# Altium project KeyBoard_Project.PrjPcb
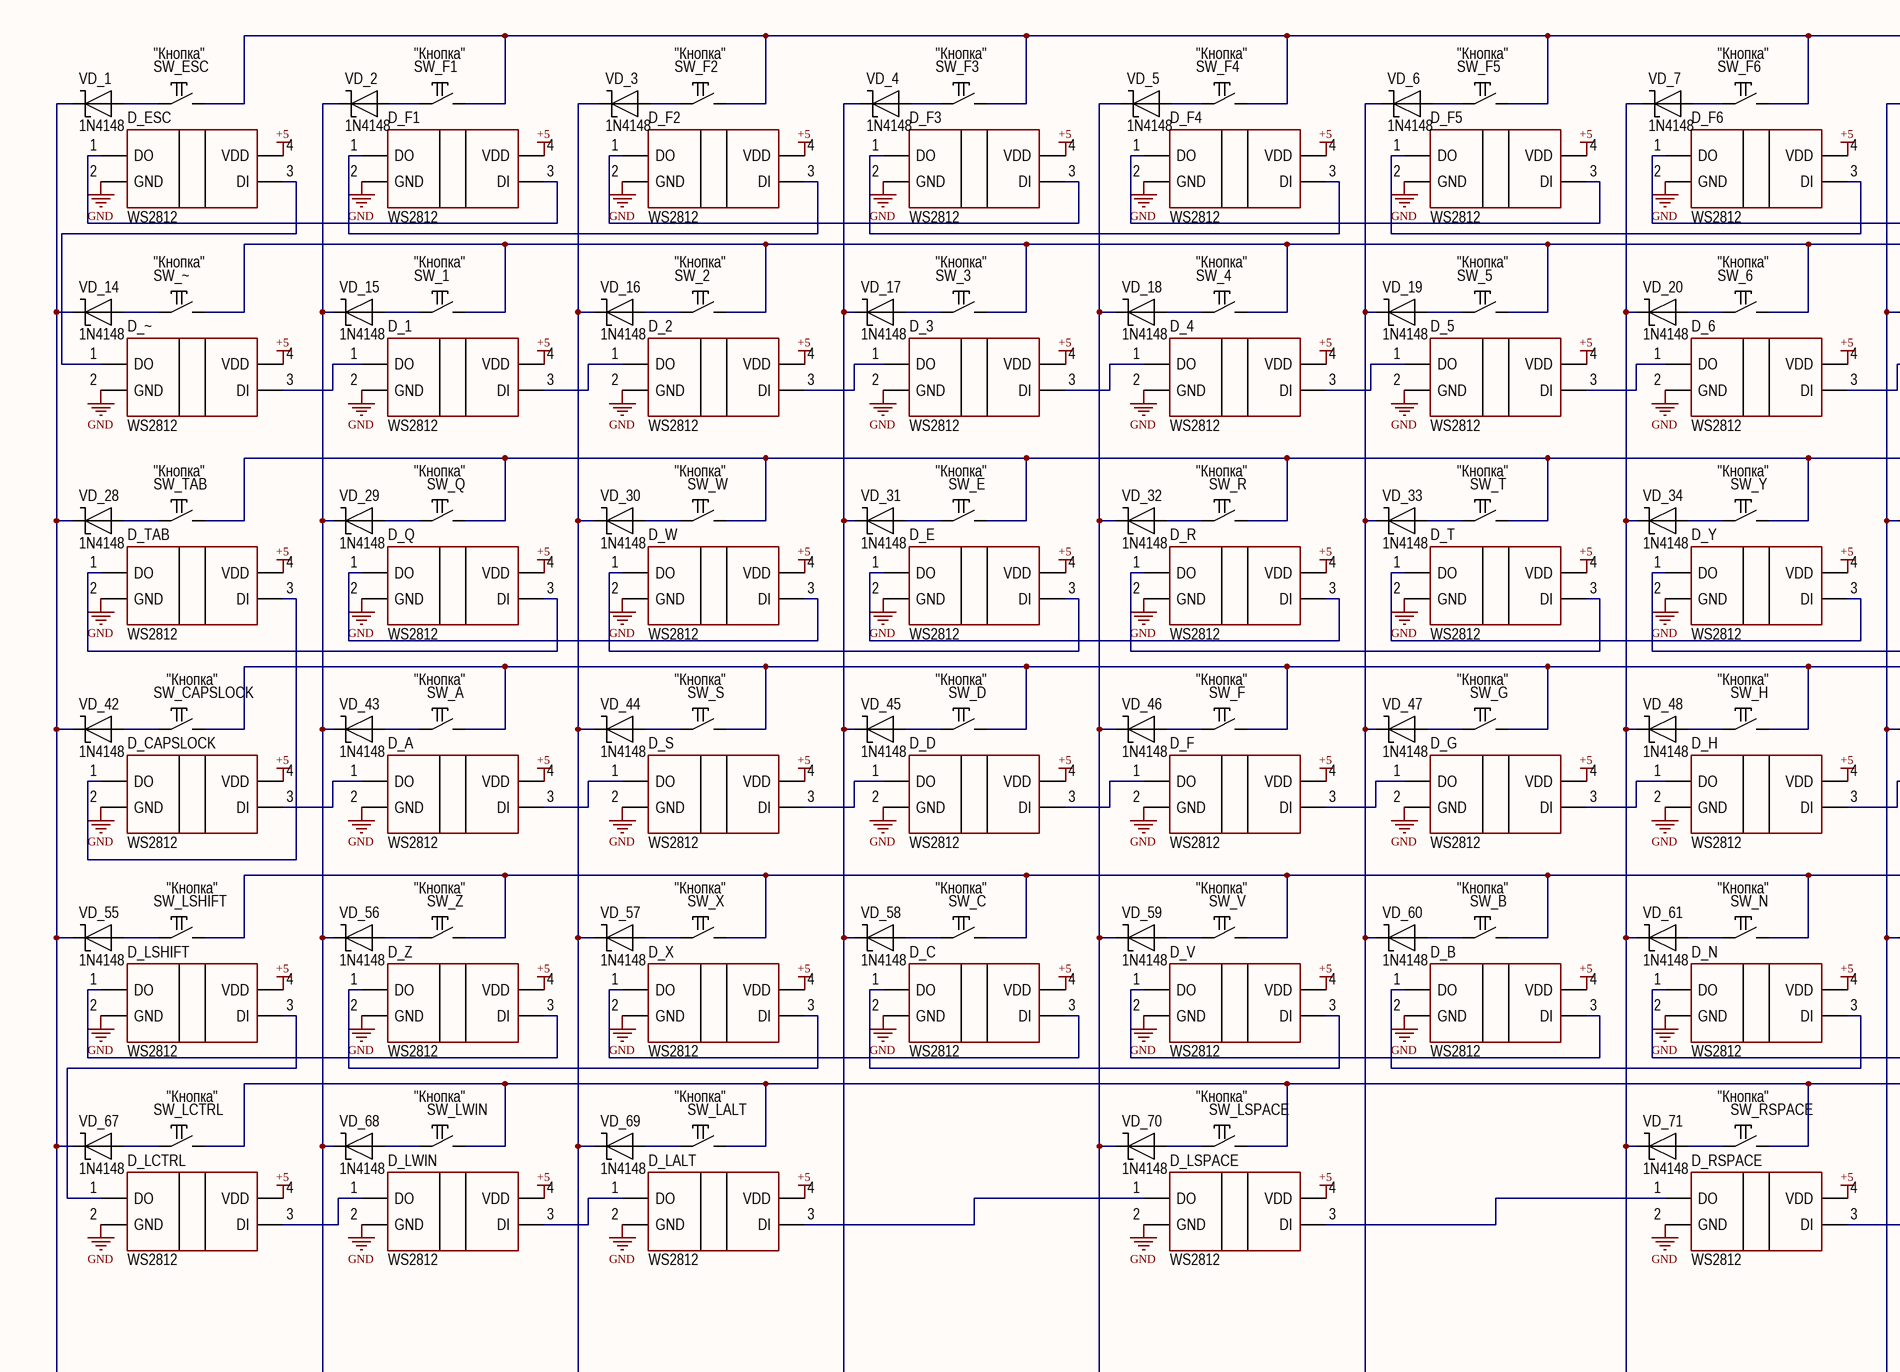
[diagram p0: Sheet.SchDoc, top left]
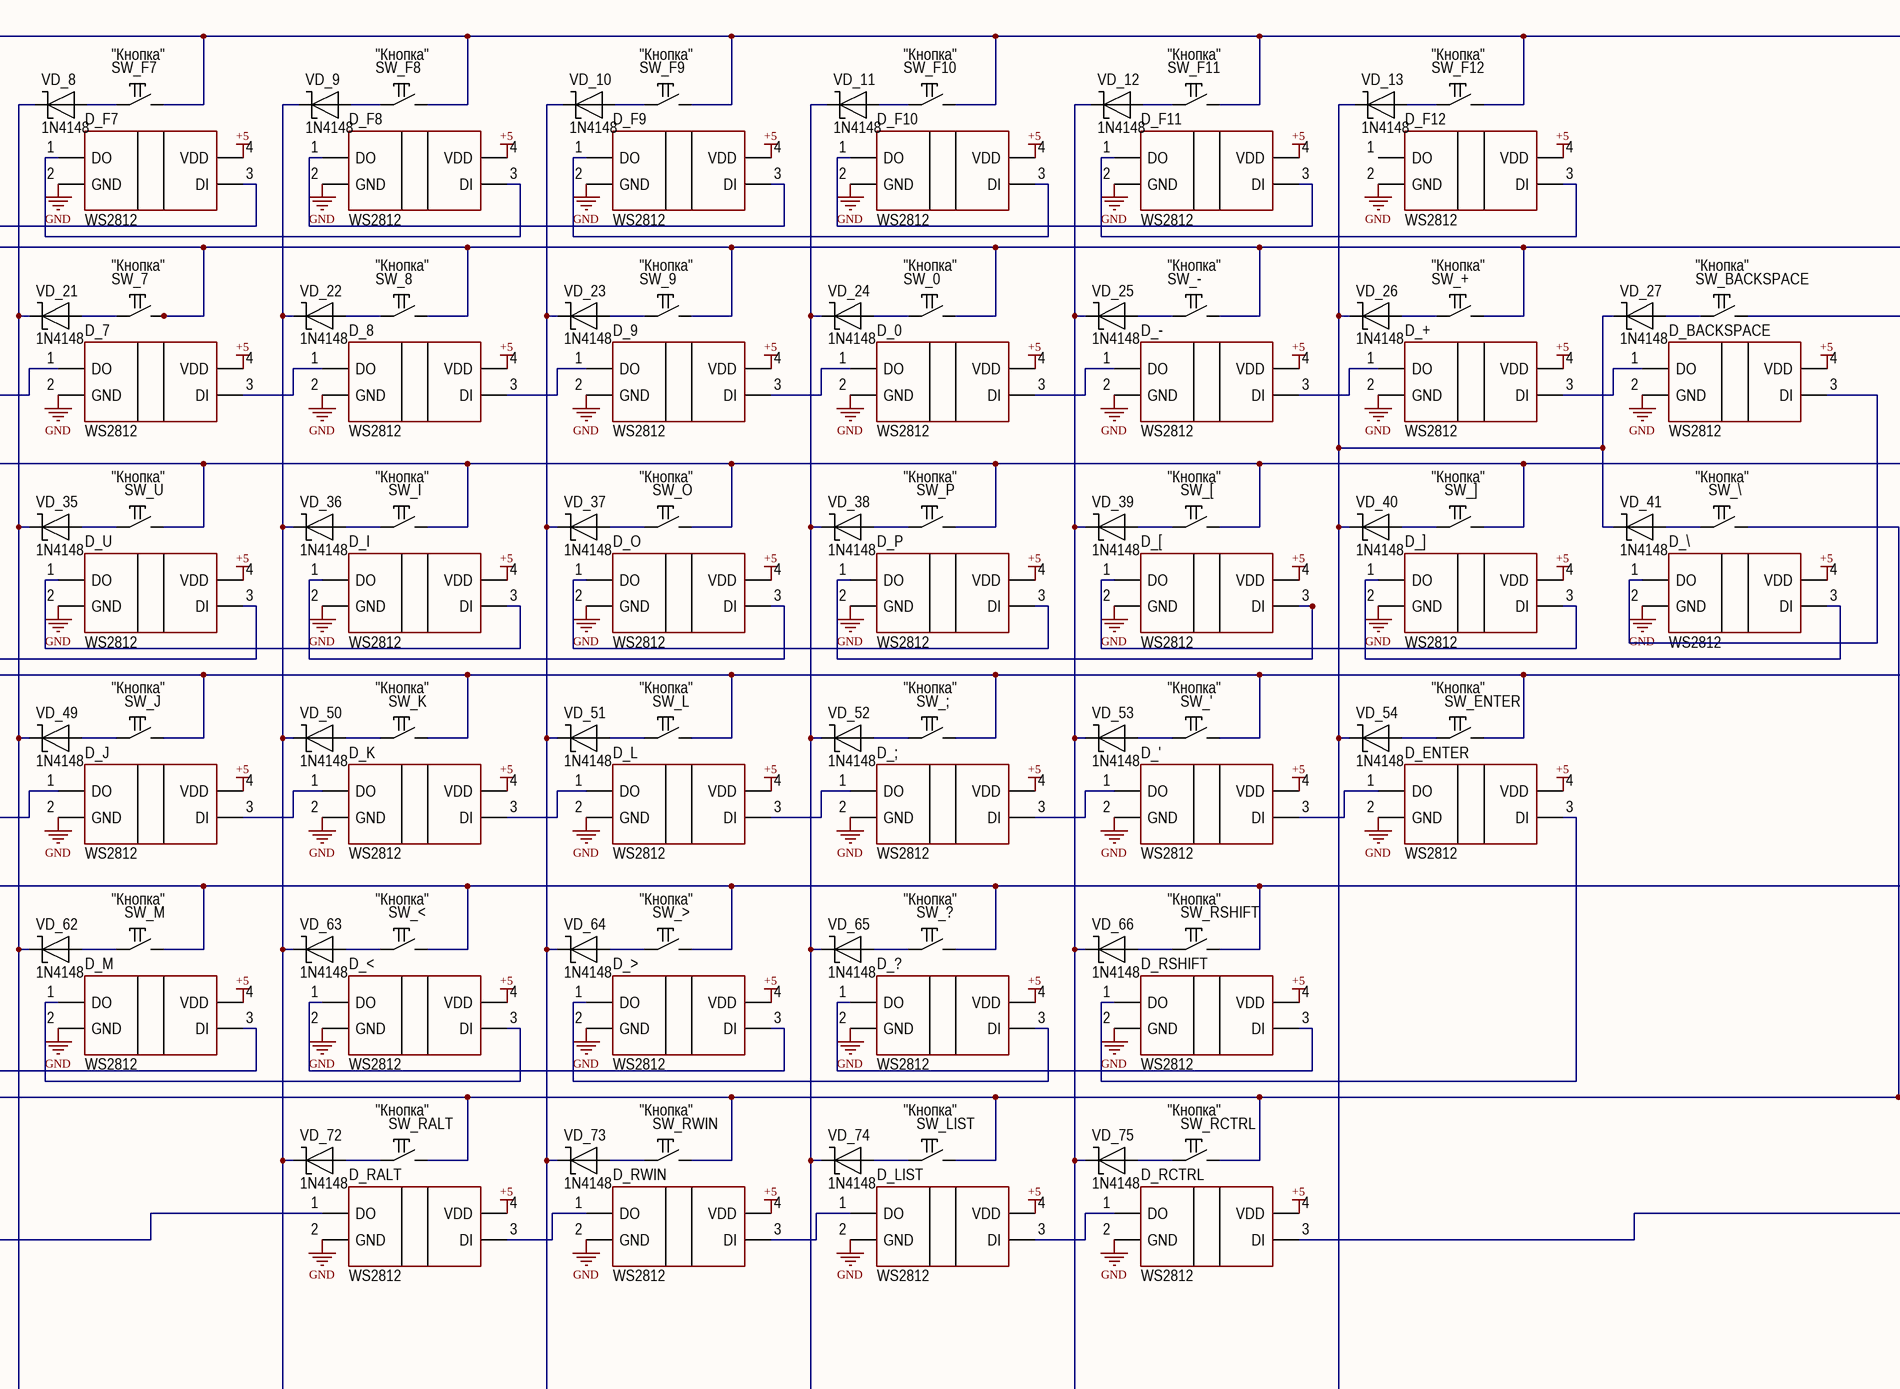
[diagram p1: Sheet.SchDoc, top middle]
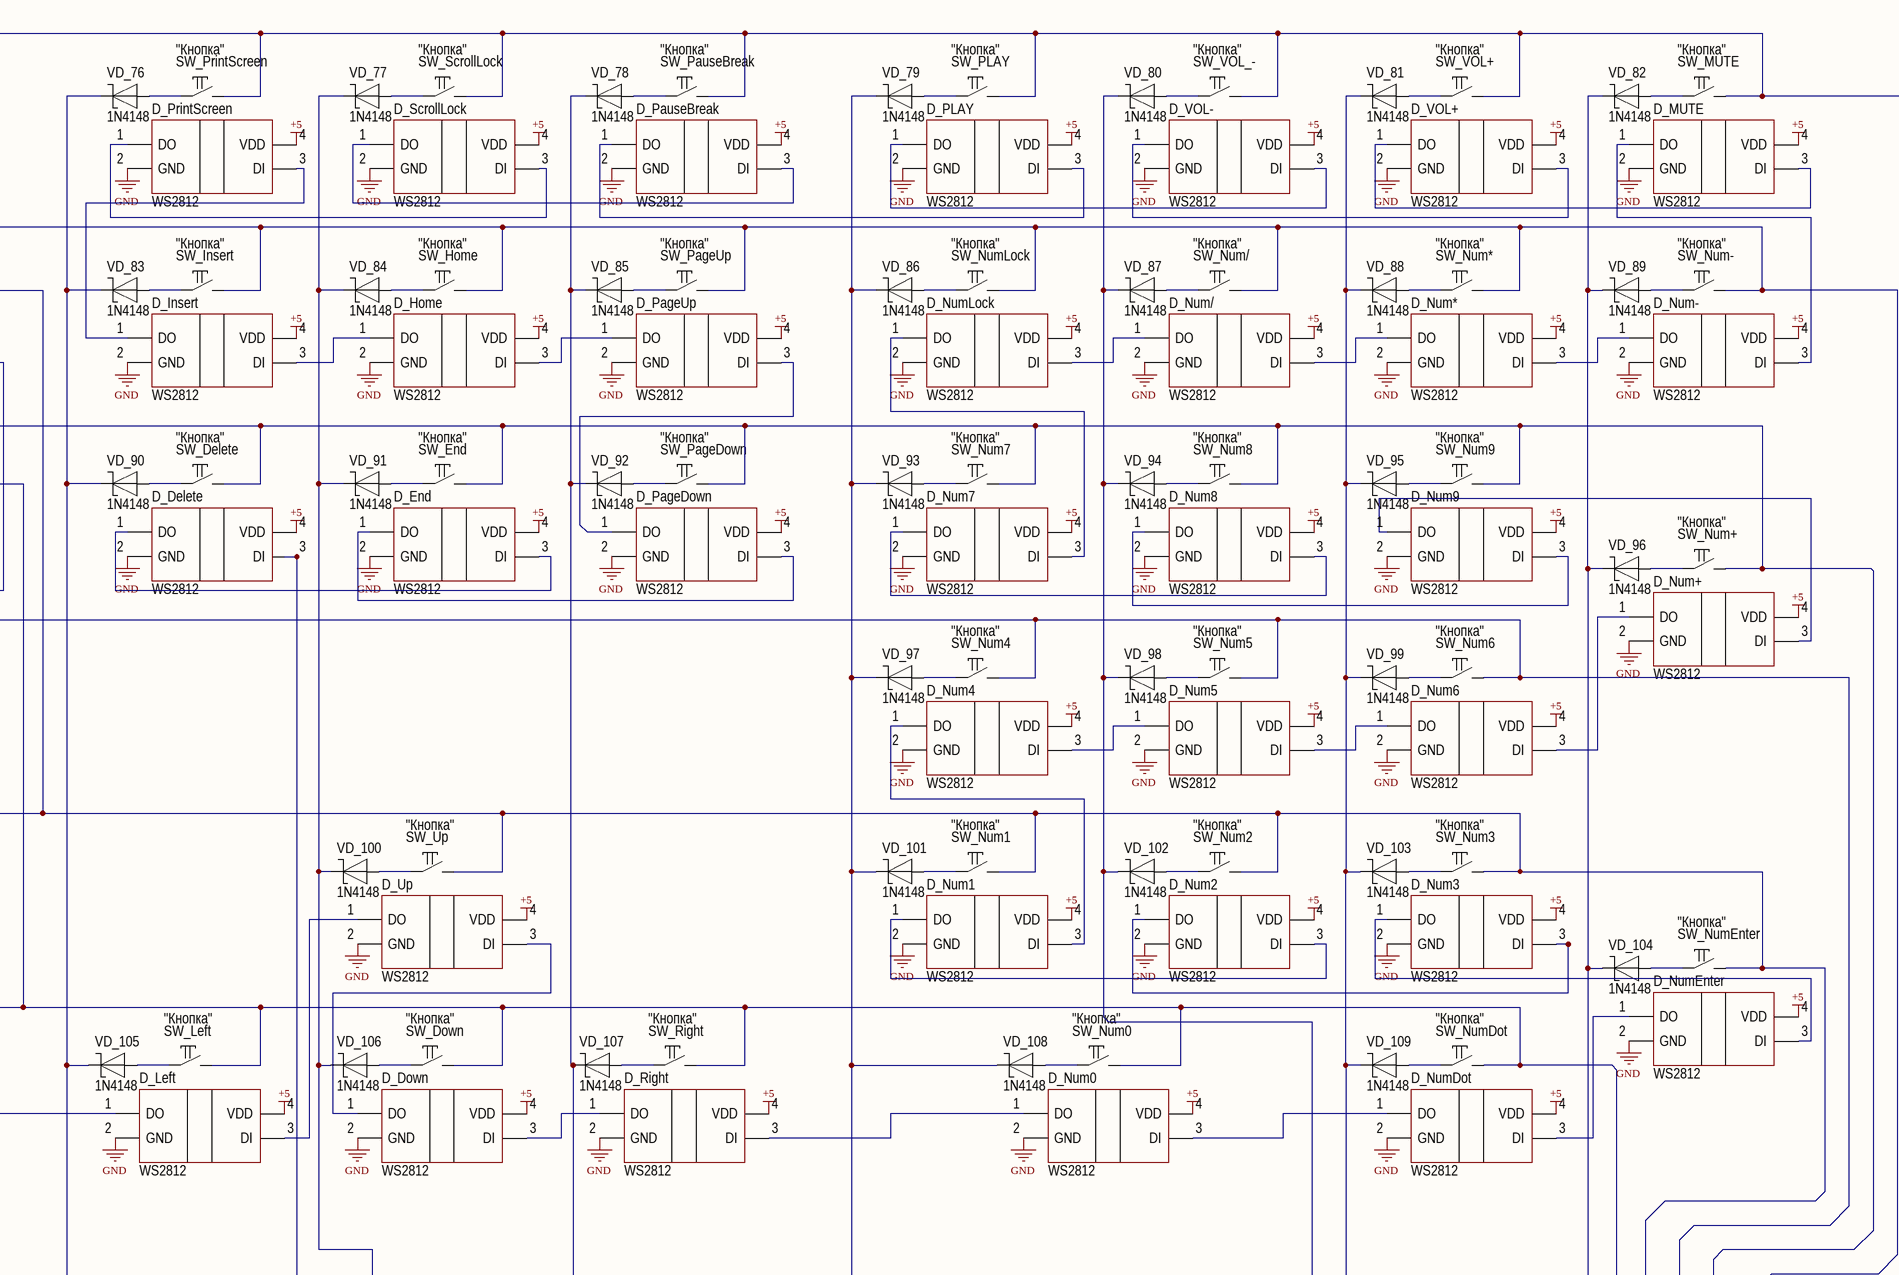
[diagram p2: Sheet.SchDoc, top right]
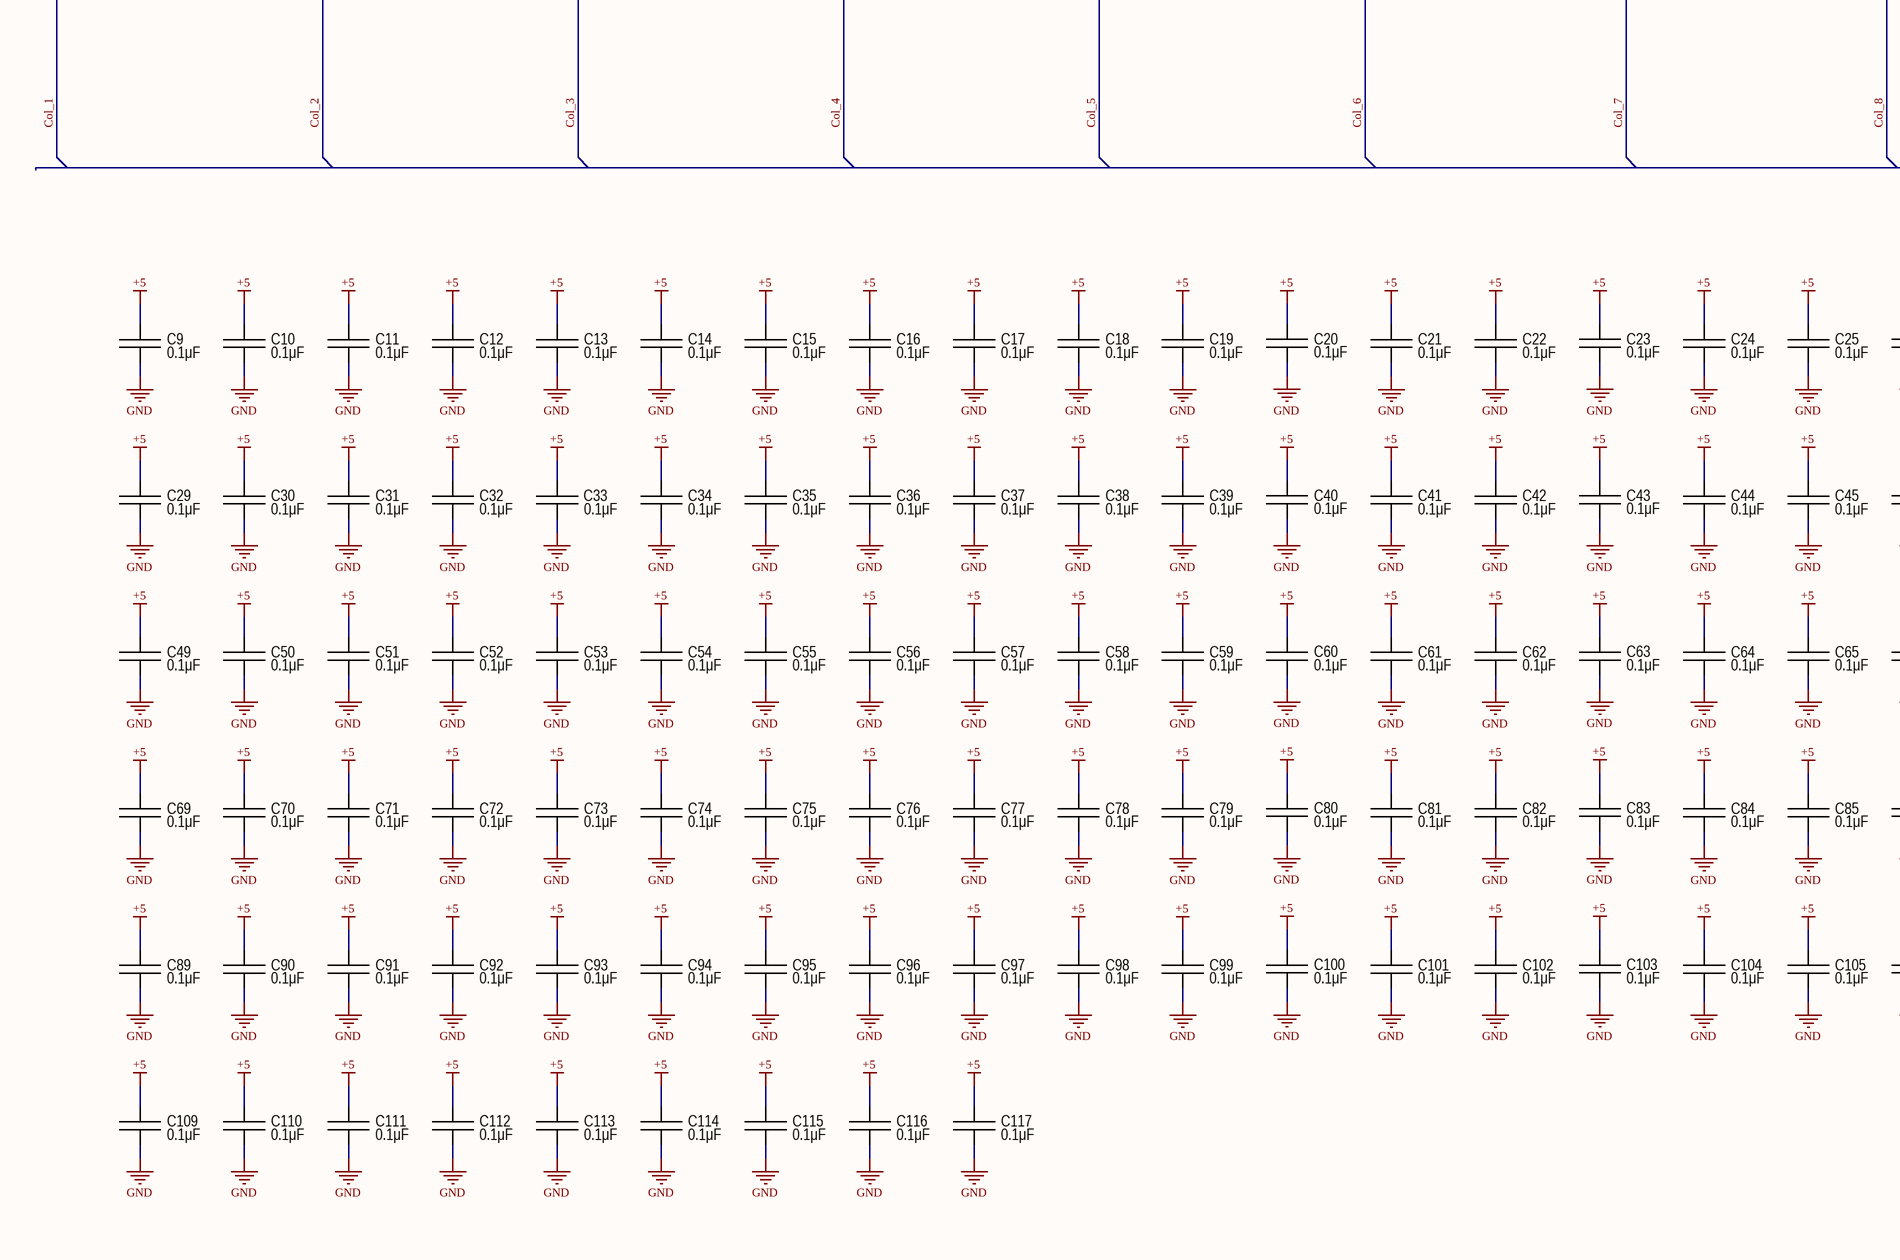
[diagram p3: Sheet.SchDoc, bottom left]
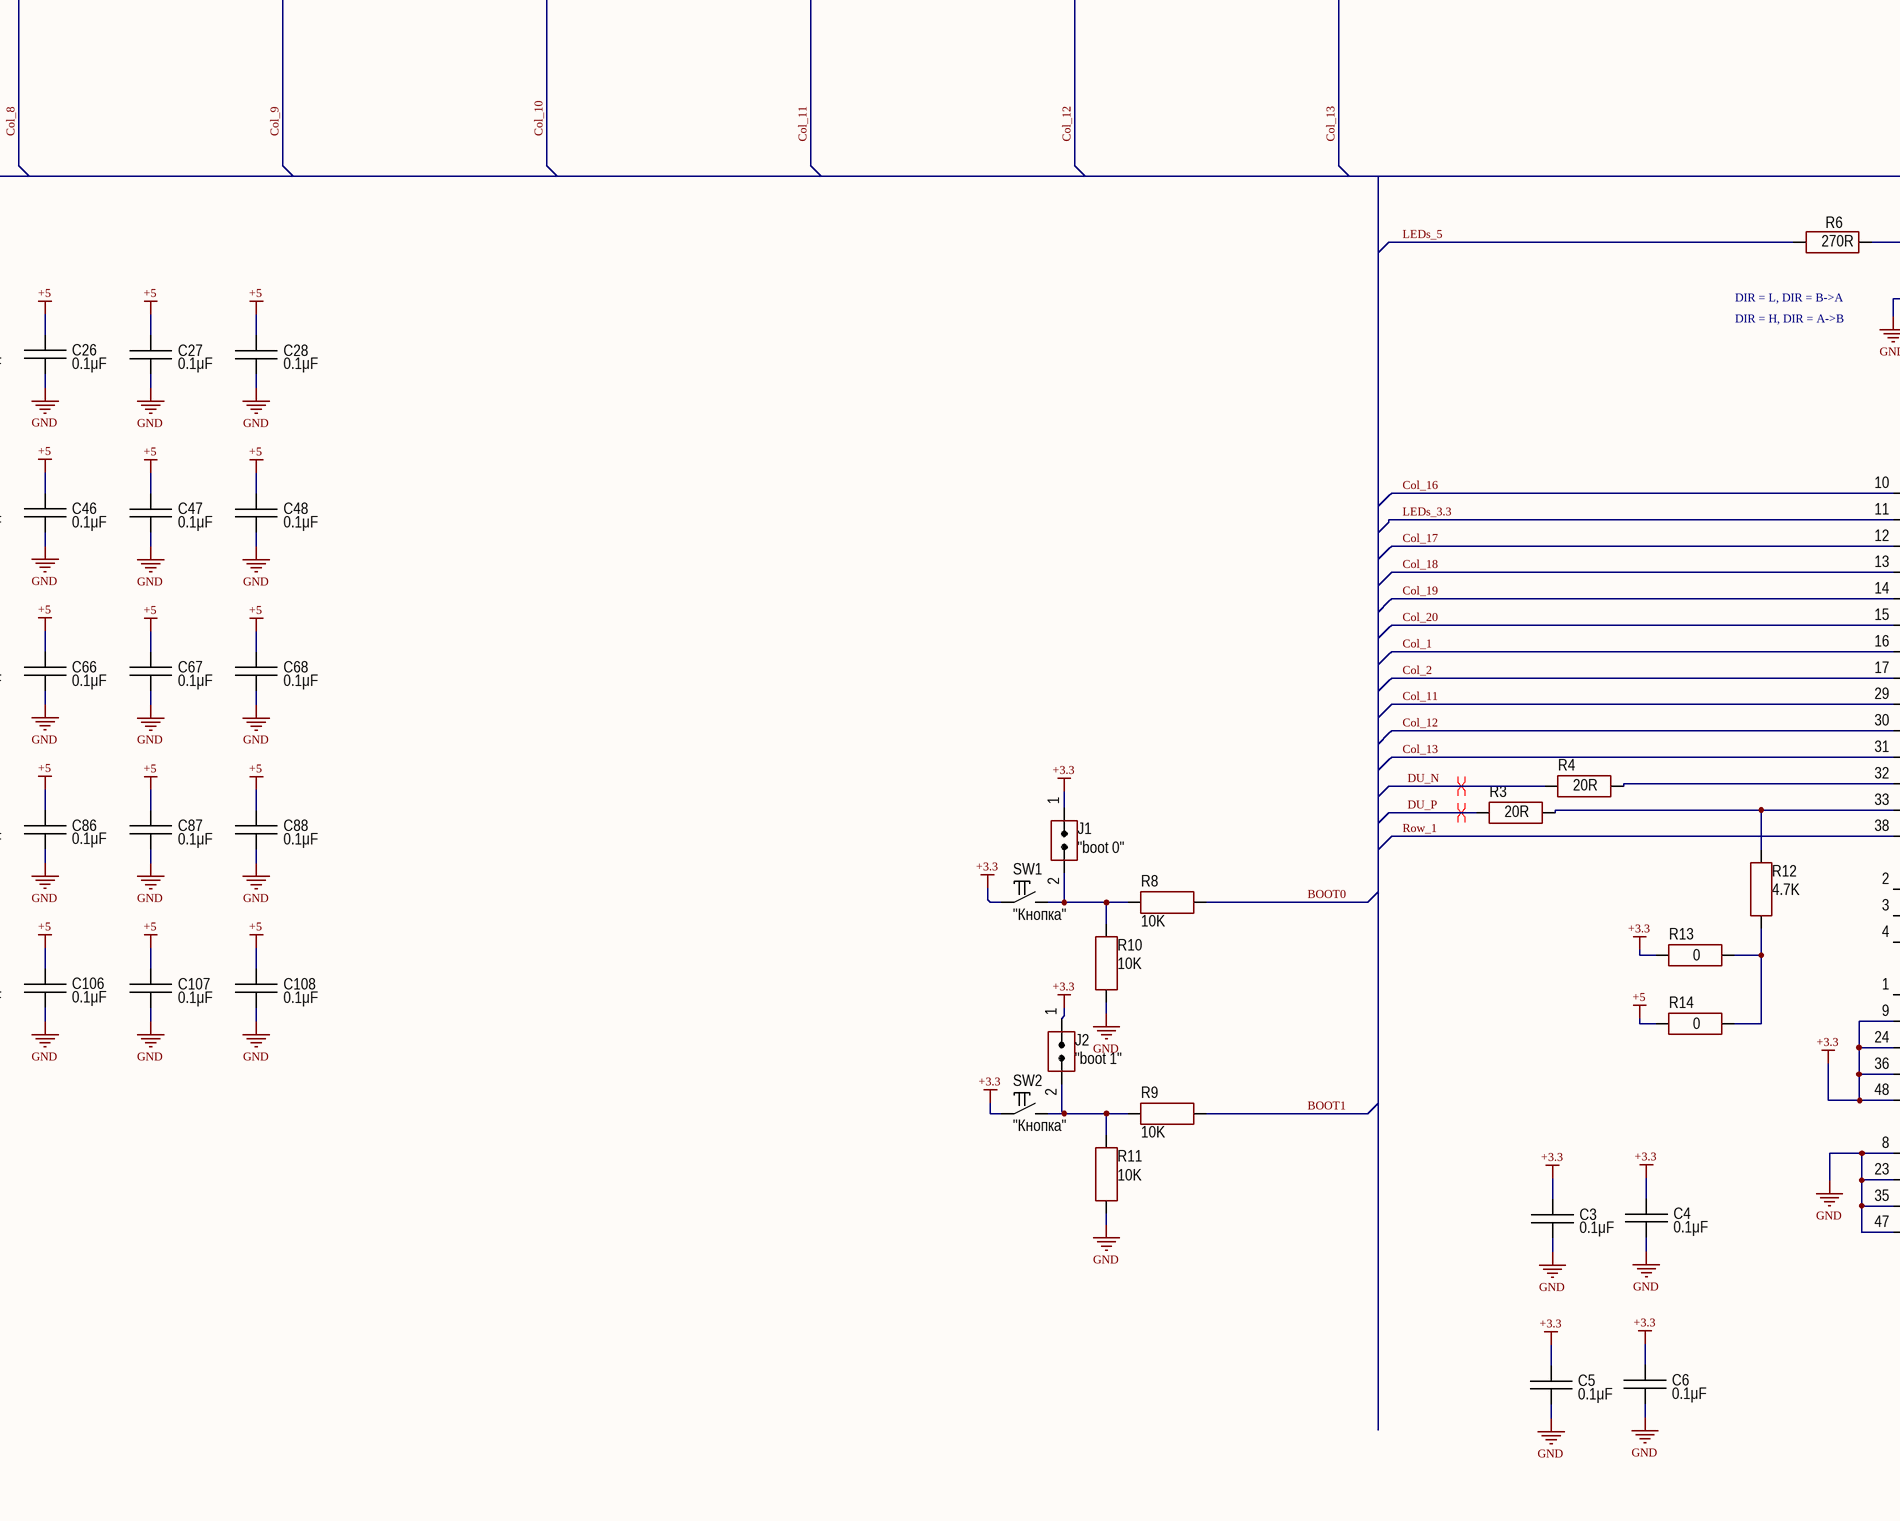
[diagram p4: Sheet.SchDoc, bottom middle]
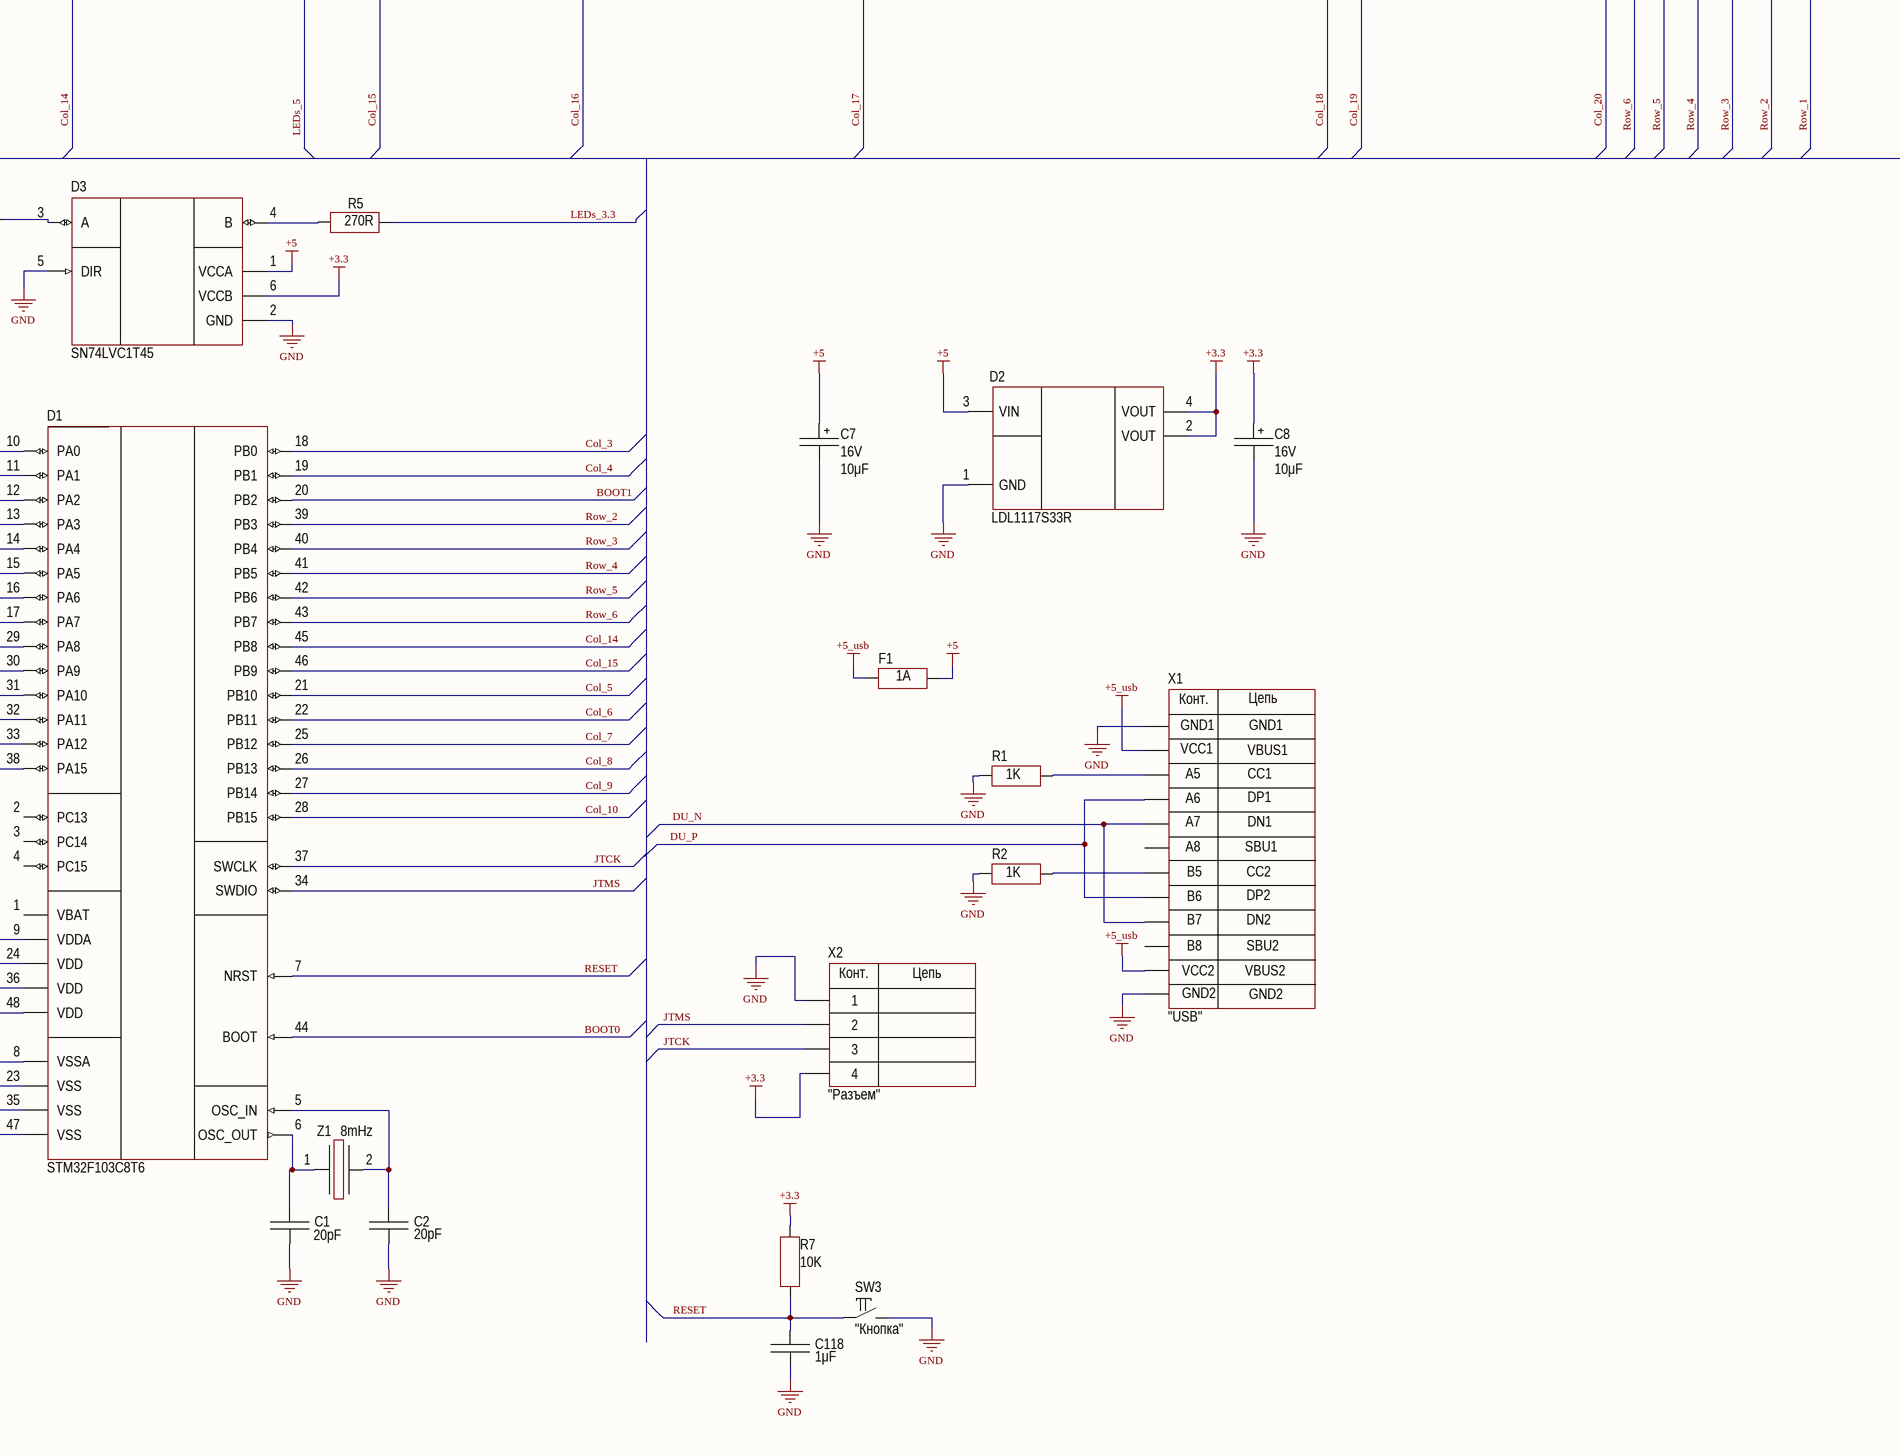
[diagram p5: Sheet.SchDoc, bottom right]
1 sheet, 471 parts. Net scope: global (net labels, ports and power ports of the same name join across sheets).
Board file: PCB.PcbDoc

## Sheet Sheet.SchDoc
size A0

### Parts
C1  value 20pF  [CAP: 0603]
C2  value 20pF  [CAP: 0603]
C3  value 0.1μF  [CAP: 0603]
C4  value 0.1μF  [CAP: 0603]
C5  value 0.1μF  [CAP: 0603]
C6  value 0.1μF  [CAP: 0603]
C7  value 10μF  Voltage: 16V  [CAP: TANTAL-A]
C8  value 10μF  Voltage: 16V  [CAP: TANTAL-A]
C9  value 0.1μF  [CAP: 0603]
C10  value 0.1μF  [CAP: 0603]
C11  value 0.1μF  [CAP: 0603]
C12  value 0.1μF  [CAP: 0603]
C13  value 0.1μF  [CAP: 0603]
C14  value 0.1μF  [CAP: 0603]
C15  value 0.1μF  [CAP: 0603]
C16  value 0.1μF  [CAP: 0603]
C17  value 0.1μF  [CAP: 0603]
C18  value 0.1μF  [CAP: 0603]
C19  value 0.1μF  [CAP: 0603]
C20  value 0.1μF  [CAP: 0603]
C21  value 0.1μF  [CAP: 0603]
C22  value 0.1μF  [CAP: 0603]
C23  value 0.1μF  [CAP: 0603]
C24  value 0.1μF  [CAP: 0603]
C25  value 0.1μF  [CAP: 0603]
C26  value 0.1μF  [CAP: 0603]
C27  value 0.1μF  [CAP: 0603]
C28  value 0.1μF  [CAP: 0603]
C29  value 0.1μF  [CAP: 0603]
C30  value 0.1μF  [CAP: 0603]
C31  value 0.1μF  [CAP: 0603]
C32  value 0.1μF  [CAP: 0603]
C33  value 0.1μF  [CAP: 0603]
C34  value 0.1μF  [CAP: 0603]
C35  value 0.1μF  [CAP: 0603]
C36  value 0.1μF  [CAP: 0603]
C37  value 0.1μF  [CAP: 0603]
C38  value 0.1μF  [CAP: 0603]
C39  value 0.1μF  [CAP: 0603]
C40  value 0.1μF  [CAP: 0603]
C41  value 0.1μF  [CAP: 0603]
C42  value 0.1μF  [CAP: 0603]
C43  value 0.1μF  [CAP: 0603]
C44  value 0.1μF  [CAP: 0603]
C45  value 0.1μF  [CAP: 0603]
C46  value 0.1μF  [CAP: 0603]
C47  value 0.1μF  [CAP: 0603]
C48  value 0.1μF  [CAP: 0603]
C49  value 0.1μF  [CAP: 0603]
C50  value 0.1μF  [CAP: 0603]
C51  value 0.1μF  [CAP: 0603]
C52  value 0.1μF  [CAP: 0603]
C53  value 0.1μF  [CAP: 0603]
C54  value 0.1μF  [CAP: 0603]
C55  value 0.1μF  [CAP: 0603]
C56  value 0.1μF  [CAP: 0603]
C57  value 0.1μF  [CAP: 0603]
C58  value 0.1μF  [CAP: 0603]
C59  value 0.1μF  [CAP: 0603]
C60  value 0.1μF  [CAP: 0603]
C61  value 0.1μF  [CAP: 0603]
C62  value 0.1μF  [CAP: 0603]
C63  value 0.1μF  [CAP: 0603]
C64  value 0.1μF  [CAP: 0603]
C65  value 0.1μF  [CAP: 0603]
C66  value 0.1μF  [CAP: 0603]
C67  value 0.1μF  [CAP: 0603]
C68  value 0.1μF  [CAP: 0603]
C69  value 0.1μF  [CAP: 0603]
C70  value 0.1μF  [CAP: 0603]
C71  value 0.1μF  [CAP: 0603]
C72  value 0.1μF  [CAP: 0603]
C73  value 0.1μF  [CAP: 0603]
C74  value 0.1μF  [CAP: 0603]
C75  value 0.1μF  [CAP: 0603]
C76  value 0.1μF  [CAP: 0603]
C77  value 0.1μF  [CAP: 0603]
C78  value 0.1μF  [CAP: 0603]
C79  value 0.1μF  [CAP: 0603]
C80  value 0.1μF  [CAP: 0603]
C81  value 0.1μF  [CAP: 0603]
C82  value 0.1μF  [CAP: 0603]
C83  value 0.1μF  [CAP: 0603]
C84  value 0.1μF  [CAP: 0603]
C85  value 0.1μF  [CAP: 0603]
C86  value 0.1μF  [CAP: 0603]
C87  value 0.1μF  [CAP: 0603]
C88  value 0.1μF  [CAP: 0603]
C89  value 0.1μF  [CAP: 0603]
C90  value 0.1μF  [CAP: 0603]
C91  value 0.1μF  [CAP: 0603]
C92  value 0.1μF  [CAP: 0603]
C93  value 0.1μF  [CAP: 0603]
C94  value 0.1μF  [CAP: 0603]
C95  value 0.1μF  [CAP: 0603]
C96  value 0.1μF  [CAP: 0603]
C97  value 0.1μF  [CAP: 0603]
C98  value 0.1μF  [CAP: 0603]
C99  value 0.1μF  [CAP: 0603]
C100  value 0.1μF  [CAP: 0603]
C101  value 0.1μF  [CAP: 0603]
C102  value 0.1μF  [CAP: 0603]
C103  value 0.1μF  [CAP: 0603]
C104  value 0.1μF  [CAP: 0603]
C105  value 0.1μF  [CAP: 0603]
C106  value 0.1μF  [CAP: 0603]
C107  value 0.1μF  [CAP: 0603]
C108  value 0.1μF  [CAP: 0603]
C109  value 0.1μF  [CAP: 0603]
C110  value 0.1μF  [CAP: 0603]
C111  value 0.1μF  [CAP: 0603]
C112  value 0.1μF  [CAP: 0603]
C113  value 0.1μF  [CAP: 0603]
C114  value 0.1μF  [CAP: 0603]
C115  value 0.1μF  [CAP: 0603]
C116  value 0.1μF  [CAP: 0603]
C117  value 0.1μF  [CAP: 0603]
C118  value 1μF  [CAP: 0603]
D1  (no value)  [48-LQFP]
D2  (no value)  [SOT223]
D3  IC CAN transceiver, 1Mbps, Half-duplex, 3...3.6V, -40...+85°C, 8-SOIC  [SOT23-6]  (value not drawn)
D_0  PartNumber: WS2812  [LED: 2020]
D_1  PartNumber: WS2812  [LED: 2020]
D_2  PartNumber: WS2812  [LED: 2020]
D_3  PartNumber: WS2812  [LED: 2020]
D_4  PartNumber: WS2812  [LED: 2020]
D_5  PartNumber: WS2812  [LED: 2020]
D_6  PartNumber: WS2812  [LED: 2020]
D_7  PartNumber: WS2812  [LED: 2020]
D_8  PartNumber: WS2812  [LED: 2020]
D_9  PartNumber: WS2812  [LED: 2020]
D_'  PartNumber: WS2812  [LED: 2020]
D_+  PartNumber: WS2812  [LED: 2020]
D_-  PartNumber: WS2812  [LED: 2020]
D_;  PartNumber: WS2812  [LED: 2020]
D_<  PartNumber: WS2812  [LED: 2020]
D_>  PartNumber: WS2812  [LED: 2020]
D_?  PartNumber: WS2812  [LED: 2020]
D_[  PartNumber: WS2812  [LED: 2020]
D_\  PartNumber: WS2812  [LED: 2020]
D_]  PartNumber: WS2812  [LED: 2020]
D_A  PartNumber: WS2812  [LED: 2020]
D_B  PartNumber: WS2812  [LED: 2020]
D_BACKSPACE  PartNumber: WS2812  [LED: 2020]
D_C  PartNumber: WS2812  [LED: 2020]
D_CAPSLOCK  PartNumber: WS2812  [LED: 2020]
D_D  PartNumber: WS2812  [LED: 2020]
D_Delete  PartNumber: WS2812  [LED: 2020]
D_Down  PartNumber: WS2812  [LED: 2020]
D_E  PartNumber: WS2812  [LED: 2020]
D_End  PartNumber: WS2812  [LED: 2020]
D_ENTER  PartNumber: WS2812  [LED: 2020]
D_ESC  PartNumber: WS2812  [LED: 2020]
D_F  PartNumber: WS2812  [LED: 2020]
D_F1  PartNumber: WS2812  [LED: 2020]
D_F2  PartNumber: WS2812  [LED: 2020]
D_F3  PartNumber: WS2812  [LED: 2020]
D_F4  PartNumber: WS2812  [LED: 2020]
D_F5  PartNumber: WS2812  [LED: 2020]
D_F6  PartNumber: WS2812  [LED: 2020]
D_F7  PartNumber: WS2812  [LED: 2020]
D_F8  PartNumber: WS2812  [LED: 2020]
D_F9  PartNumber: WS2812  [LED: 2020]
D_F10  PartNumber: WS2812  [LED: 2020]
D_F11  PartNumber: WS2812  [LED: 2020]
D_F12  PartNumber: WS2812  [LED: 2020]
D_G  PartNumber: WS2812  [LED: 2020]
D_H  PartNumber: WS2812  [LED: 2020]
D_Home  PartNumber: WS2812  [LED: 2020]
D_I  PartNumber: WS2812  [LED: 2020]
D_Insert  PartNumber: WS2812  [LED: 2020]
D_J  PartNumber: WS2812  [LED: 2020]
D_K  PartNumber: WS2812  [LED: 2020]
D_L  PartNumber: WS2812  [LED: 2020]
D_LALT  PartNumber: WS2812  [LED: 2020]
D_LCTRL  PartNumber: WS2812  [LED: 2020]
D_Left  PartNumber: WS2812  [LED: 2020]
D_LIST  PartNumber: WS2812  [LED: 2020]
D_LSHIFT  PartNumber: WS2812  [LED: 2020]
D_LSPACE  PartNumber: WS2812  [LED: 2020]
D_LWIN  PartNumber: WS2812  [LED: 2020]
D_M  PartNumber: WS2812  [LED: 2020]
D_MUTE  PartNumber: WS2812  [LED: 2020]
D_N  PartNumber: WS2812  [LED: 2020]
D_Num0  PartNumber: WS2812  [LED: 2020]
D_Num1  PartNumber: WS2812  [LED: 2020]
D_Num2  PartNumber: WS2812  [LED: 2020]
D_Num3  PartNumber: WS2812  [LED: 2020]
D_Num4  PartNumber: WS2812  [LED: 2020]
D_Num5  PartNumber: WS2812  [LED: 2020]
D_Num6  PartNumber: WS2812  [LED: 2020]
D_Num7  PartNumber: WS2812  [LED: 2020]
D_Num8  PartNumber: WS2812  [LED: 2020]
D_Num9  PartNumber: WS2812  [LED: 2020]
D_Num*  PartNumber: WS2812  [LED: 2020]
D_Num+  PartNumber: WS2812  [LED: 2020]
D_Num-  PartNumber: WS2812  [LED: 2020]
D_Num/  PartNumber: WS2812  [LED: 2020]
D_NumDot  PartNumber: WS2812  [LED: 2020]
D_NumEnter  PartNumber: WS2812  [LED: 2020]
D_NumLock  PartNumber: WS2812  [LED: 2020]
D_O  PartNumber: WS2812  [LED: 2020]
D_P  PartNumber: WS2812  [LED: 2020]
D_PageDown  PartNumber: WS2812  [LED: 2020]
D_PageUp  PartNumber: WS2812  [LED: 2020]
D_PauseBreak  PartNumber: WS2812  [LED: 2020]
D_PLAY  PartNumber: WS2812  [LED: 2020]
D_PrintScreen  PartNumber: WS2812  [LED: 2020]
D_Q  PartNumber: WS2812  [LED: 2020]
D_R  PartNumber: WS2812  [LED: 2020]
D_RALT  PartNumber: WS2812  [LED: 2020]
D_RCTRL  PartNumber: WS2812  [LED: 2020]
D_Right  PartNumber: WS2812  [LED: 2020]
D_RSHIFT  PartNumber: WS2812  [LED: 2020]
D_RSPACE  PartNumber: WS2812  [LED: 2020]
D_RWIN  PartNumber: WS2812  [LED: 2020]
D_S  PartNumber: WS2812  [LED: 2020]
D_ScrollLock  PartNumber: WS2812  [LED: 2020]
D_T  PartNumber: WS2812  [LED: 2020]
D_TAB  PartNumber: WS2812  [LED: 2020]
D_U  PartNumber: WS2812  [LED: 2020]
D_Up  PartNumber: WS2812  [LED: 2020]
D_V  PartNumber: WS2812  [LED: 2020]
D_VOL+  PartNumber: WS2812  [LED: 2020]
D_VOL-  PartNumber: WS2812  [LED: 2020]
D_W  PartNumber: WS2812  [LED: 2020]
D_X  PartNumber: WS2812  [LED: 2020]
D_Y  PartNumber: WS2812  [LED: 2020]
D_Z  PartNumber: WS2812  [LED: 2020]
D_~  PartNumber: WS2812  [LED: 2020]
F1  value 1A  [RES: 1206]  (hidden comment: Resistor film, 1A, , 1206, 0.25W, -55...+125°C)
J1  CommentText: "boot 0"  [CON: JUMPER x1]
J2  CommentText: "boot 1"  [CON: JUMPER x1]
R1  value 1K  [RES: 0603]  (hidden comment: Resistor film, 1K, , 0603, 0.1W, -55...+125°C)
R2  value 1K  [RES: 0603]  (hidden comment: Resistor film, 1K, , 0603, 0.1W, -55...+125°C)
R3  value 20R  [RES: 0603]  (hidden comment: Resistor film, 1K, , 0603, 0.1W, -55...+125°C)
R4  value 20R  [RES: 0603]  (hidden comment: Resistor film, 1K, , 0603, 0.1W, -55...+125°C)
R5  value 270R  [RES: 0603]  (hidden comment: Resistor film, 270R, , 0603, 0.1W, -55...+125°C)
R6  value 270R  [RES: 0603]  (hidden comment: Resistor film, 270R, , 0603, 0.1W, -55...+125°C)
R7  value 10K  [RES: 0603]  (hidden comment: Resistor film, 270R, , 0603, 0.1W, -55...+125°C)
R8  value 10K  [RES: 0603]  (hidden comment: Resistor film, 270R, , 0603, 0.1W, -55...+125°C)
R9  value 10K  [RES: 0603]  (hidden comment: Resistor film, 270R, , 0603, 0.1W, -55...+125°C)
R10  value 10K  [RES: 0603]  (hidden comment: Resistor film, 270R, , 0603, 0.1W, -55...+125°C)
R11  value 10K  [RES: 0603]  (hidden comment: Resistor film, 270R, , 0603, 0.1W, -55...+125°C)
R12  value 4.7K  [RES: 0603]  (hidden comment: Resistor film, 270R, , 0603, 0.1W, -55...+125°C)
R13  value 0  [RES: 0603]  (hidden comment: Resistor film, 270R, , 0603, 0.1W, -55...+125°C)
R14  value 0  [RES: 0603]  (hidden comment: Resistor film, 270R, , 0603, 0.1W, -55...+125°C)
SW1  CommentText: "Кнопка"  [BUT: 3x4x2 SMT]
SW2  CommentText: "Кнопка"  [BUT: 3x4x2 SMT]
SW3  CommentText: "Кнопка"  [BUT: 3x4x2 SMT]
SW_0  CommentText: "Кнопка"  [BUT: kailh]
SW_1  CommentText: "Кнопка"  [BUT: kailh]
SW_2  CommentText: "Кнопка"  [BUT: kailh]
SW_3  CommentText: "Кнопка"  [BUT: kailh]
SW_4  CommentText: "Кнопка"  [BUT: kailh]
SW_5  CommentText: "Кнопка"  [BUT: kailh]
SW_6  CommentText: "Кнопка"  [BUT: kailh]
SW_7  CommentText: "Кнопка"  [BUT: kailh]
SW_8  CommentText: "Кнопка"  [BUT: kailh]
SW_9  CommentText: "Кнопка"  [BUT: kailh]
SW_'  CommentText: "Кнопка"  [BUT: kailh]
SW_+  CommentText: "Кнопка"  [BUT: kailh]
SW_-  CommentText: "Кнопка"  [BUT: kailh]
SW_;  CommentText: "Кнопка"  [BUT: kailh]
SW_<  CommentText: "Кнопка"  [BUT: kailh]
SW_>  CommentText: "Кнопка"  [BUT: kailh]
SW_?  CommentText: "Кнопка"  [BUT: kailh]
SW_[  CommentText: "Кнопка"  [BUT: kailh]
SW_\  CommentText: "Кнопка"  [BUT: kailh]
SW_]  CommentText: "Кнопка"  [BUT: kailh]
SW_A  CommentText: "Кнопка"  [BUT: kailh]
SW_B  CommentText: "Кнопка"  [BUT: kailh]
SW_BACKSPACE  CommentText: "Кнопка"  [BUT: kailh]
SW_C  CommentText: "Кнопка"  [BUT: kailh]
SW_CAPSLOCK  CommentText: "Кнопка"  [BUT: kailh]
SW_D  CommentText: "Кнопка"  [BUT: kailh]
SW_Delete  CommentText: "Кнопка"  [BUT: kailh]
SW_Down  CommentText: "Кнопка"  [BUT: kailh]
SW_E  CommentText: "Кнопка"  [BUT: kailh]
SW_End  CommentText: "Кнопка"  [BUT: kailh]
SW_ENTER  CommentText: "Кнопка"  [BUT: kailh]
SW_ESC  CommentText: "Кнопка"  [BUT: kailh]
SW_F  CommentText: "Кнопка"  [BUT: kailh]
SW_F1  CommentText: "Кнопка"  [BUT: kailh]
SW_F2  CommentText: "Кнопка"  [BUT: kailh]
SW_F3  CommentText: "Кнопка"  [BUT: kailh]
SW_F4  CommentText: "Кнопка"  [BUT: kailh]
SW_F5  CommentText: "Кнопка"  [BUT: kailh]
SW_F6  CommentText: "Кнопка"  [BUT: kailh]
SW_F7  CommentText: "Кнопка"  [BUT: kailh]
SW_F8  CommentText: "Кнопка"  [BUT: kailh]
SW_F9  CommentText: "Кнопка"  [BUT: kailh]
SW_F10  CommentText: "Кнопка"  [BUT: kailh]
SW_F11  CommentText: "Кнопка"  [BUT: kailh]
SW_F12  CommentText: "Кнопка"  [BUT: kailh]
SW_G  CommentText: "Кнопка"  [BUT: kailh]
SW_H  CommentText: "Кнопка"  [BUT: kailh]
SW_Home  CommentText: "Кнопка"  [BUT: kailh]
SW_I  CommentText: "Кнопка"  [BUT: kailh]
SW_Insert  CommentText: "Кнопка"  [BUT: kailh]
SW_J  CommentText: "Кнопка"  [BUT: kailh]
SW_K  CommentText: "Кнопка"  [BUT: kailh]
SW_L  CommentText: "Кнопка"  [BUT: kailh]
SW_LALT  CommentText: "Кнопка"  [BUT: kailh]
SW_LCTRL  CommentText: "Кнопка"  [BUT: kailh]
SW_Left  CommentText: "Кнопка"  [BUT: kailh]
SW_LIST  CommentText: "Кнопка"  [BUT: kailh]
SW_LSHIFT  CommentText: "Кнопка"  [BUT: kailh]
SW_LSPACE  CommentText: "Кнопка"  [BUT: kailh]
SW_LWIN  CommentText: "Кнопка"  [BUT: kailh]
SW_M  CommentText: "Кнопка"  [BUT: kailh]
SW_MUTE  CommentText: "Кнопка"  [BUT: kailh]
SW_N  CommentText: "Кнопка"  [BUT: kailh]
SW_Num0  CommentText: "Кнопка"  [BUT: kailh]
SW_Num1  CommentText: "Кнопка"  [BUT: kailh]
SW_Num2  CommentText: "Кнопка"  [BUT: kailh]
SW_Num3  CommentText: "Кнопка"  [BUT: kailh]
SW_Num4  CommentText: "Кнопка"  [BUT: kailh]
SW_Num5  CommentText: "Кнопка"  [BUT: kailh]
SW_Num6  CommentText: "Кнопка"  [BUT: kailh]
SW_Num7  CommentText: "Кнопка"  [BUT: kailh]
SW_Num8  CommentText: "Кнопка"  [BUT: kailh]
SW_Num9  CommentText: "Кнопка"  [BUT: kailh]
SW_Num*  CommentText: "Кнопка"  [BUT: kailh]
SW_Num+  CommentText: "Кнопка"  [BUT: kailh]
SW_Num-  CommentText: "Кнопка"  [BUT: kailh]
SW_Num/  CommentText: "Кнопка"  [BUT: kailh]
SW_NumDot  CommentText: "Кнопка"  [BUT: kailh]
SW_NumEnter  CommentText: "Кнопка"  [BUT: kailh]
SW_NumLock  CommentText: "Кнопка"  [BUT: kailh]
SW_O  CommentText: "Кнопка"  [BUT: kailh]
SW_P  CommentText: "Кнопка"  [BUT: kailh]
SW_PageDown  CommentText: "Кнопка"  [BUT: kailh]
SW_PageUp  CommentText: "Кнопка"  [BUT: kailh]
SW_PauseBreak  CommentText: "Кнопка"  [BUT: kailh]
SW_PLAY  CommentText: "Кнопка"  [BUT: kailh]
SW_PrintScreen  CommentText: "Кнопка"  [BUT: kailh]
SW_Q  CommentText: "Кнопка"  [BUT: kailh]
SW_R  CommentText: "Кнопка"  [BUT: kailh]
SW_RALT  CommentText: "Кнопка"  [BUT: kailh]
SW_RCTRL  CommentText: "Кнопка"  [BUT: kailh]
SW_Right  CommentText: "Кнопка"  [BUT: kailh]
SW_RSHIFT  CommentText: "Кнопка"  [BUT: kailh]
SW_RSPACE  CommentText: "Кнопка"  [BUT: kailh]
SW_RWIN  CommentText: "Кнопка"  [BUT: kailh]
SW_S  CommentText: "Кнопка"  [BUT: kailh]
SW_ScrollLock  CommentText: "Кнопка"  [BUT: kailh]
SW_T  CommentText: "Кнопка"  [BUT: kailh]
SW_TAB  CommentText: "Кнопка"  [BUT: kailh]
SW_U  CommentText: "Кнопка"  [BUT: kailh]
SW_Up  CommentText: "Кнопка"  [BUT: kailh]
SW_V  CommentText: "Кнопка"  [BUT: kailh]
SW_VOL+  CommentText: "Кнопка"  [BUT: kailh]
SW_VOL_-  CommentText: "Кнопка"  [BUT: kailh]
SW_W  CommentText: "Кнопка"  [BUT: kailh]
SW_X  CommentText: "Кнопка"  [BUT: kailh]
SW_Y  CommentText: "Кнопка"  [BUT: kailh]
SW_Z  CommentText: "Кнопка"  [BUT: kailh]
SW_~  CommentText: "Кнопка"  [BUT: kailh]
VD_1  PartNumber: 1N4148  [DIODE: SOD323]
VD_2  PartNumber: 1N4148  [DIODE: SOD323]
VD_3  PartNumber: 1N4148  [DIODE: SOD323]
VD_4  PartNumber: 1N4148  [DIODE: SOD323]
VD_5  PartNumber: 1N4148  [DIODE: SOD323]
VD_6  PartNumber: 1N4148  [DIODE: SOD323]
VD_7  PartNumber: 1N4148  [DIODE: SOD323]
VD_8  PartNumber: 1N4148  [DIODE: SOD323]
VD_9  PartNumber: 1N4148  [DIODE: SOD323]
VD_10  PartNumber: 1N4148  [DIODE: SOD323]
VD_11  PartNumber: 1N4148  [DIODE: SOD323]
VD_12  PartNumber: 1N4148  [DIODE: SOD323]
VD_13  PartNumber: 1N4148  [DIODE: SOD323]
VD_14  PartNumber: 1N4148  [DIODE: SOD323]
VD_15  PartNumber: 1N4148  [DIODE: SOD323]
VD_16  PartNumber: 1N4148  [DIODE: SOD323]
VD_17  PartNumber: 1N4148  [DIODE: SOD323]
VD_18  PartNumber: 1N4148  [DIODE: SOD323]
VD_19  PartNumber: 1N4148  [DIODE: SOD323]
VD_20  PartNumber: 1N4148  [DIODE: SOD323]
VD_21  PartNumber: 1N4148  [DIODE: SOD323]
VD_22  PartNumber: 1N4148  [DIODE: SOD323]
VD_23  PartNumber: 1N4148  [DIODE: SOD323]
VD_24  PartNumber: 1N4148  [DIODE: SOD323]
VD_25  PartNumber: 1N4148  [DIODE: SOD323]
VD_26  PartNumber: 1N4148  [DIODE: SOD323]
VD_27  PartNumber: 1N4148  [DIODE: SOD323]
VD_28  PartNumber: 1N4148  [DIODE: SOD323]
VD_29  PartNumber: 1N4148  [DIODE: SOD323]
VD_30  PartNumber: 1N4148  [DIODE: SOD323]
VD_31  PartNumber: 1N4148  [DIODE: SOD323]
VD_32  PartNumber: 1N4148  [DIODE: SOD323]
VD_33  PartNumber: 1N4148  [DIODE: SOD323]
VD_34  PartNumber: 1N4148  [DIODE: SOD323]
VD_35  PartNumber: 1N4148  [DIODE: SOD323]
VD_36  PartNumber: 1N4148  [DIODE: SOD323]
VD_37  PartNumber: 1N4148  [DIODE: SOD323]
VD_38  PartNumber: 1N4148  [DIODE: SOD323]
VD_39  PartNumber: 1N4148  [DIODE: SOD323]
VD_40  PartNumber: 1N4148  [DIODE: SOD323]
VD_41  PartNumber: 1N4148  [DIODE: SOD323]
VD_42  PartNumber: 1N4148  [DIODE: SOD323]
VD_43  PartNumber: 1N4148  [DIODE: SOD323]
VD_44  PartNumber: 1N4148  [DIODE: SOD323]
VD_45  PartNumber: 1N4148  [DIODE: SOD323]
VD_46  PartNumber: 1N4148  [DIODE: SOD323]
VD_47  PartNumber: 1N4148  [DIODE: SOD323]
VD_48  PartNumber: 1N4148  [DIODE: SOD323]
VD_49  PartNumber: 1N4148  [DIODE: SOD323]
VD_50  PartNumber: 1N4148  [DIODE: SOD323]
VD_51  PartNumber: 1N4148  [DIODE: SOD323]
VD_52  PartNumber: 1N4148  [DIODE: SOD323]
VD_53  PartNumber: 1N4148  [DIODE: SOD323]
VD_54  PartNumber: 1N4148  [DIODE: SOD323]
VD_55  PartNumber: 1N4148  [DIODE: SOD323]
VD_56  PartNumber: 1N4148  [DIODE: SOD323]
VD_57  PartNumber: 1N4148  [DIODE: SOD323]
VD_58  PartNumber: 1N4148  [DIODE: SOD323]
VD_59  PartNumber: 1N4148  [DIODE: SOD323]
VD_60  PartNumber: 1N4148  [DIODE: SOD323]
VD_61  PartNumber: 1N4148  [DIODE: SOD323]
VD_62  PartNumber: 1N4148  [DIODE: SOD323]
VD_63  PartNumber: 1N4148  [DIODE: SOD323]
VD_64  PartNumber: 1N4148  [DIODE: SOD323]
VD_65  PartNumber: 1N4148  [DIODE: SOD323]
VD_66  PartNumber: 1N4148  [DIODE: SOD323]
VD_67  PartNumber: 1N4148  [DIODE: SOD323]
VD_68  PartNumber: 1N4148  [DIODE: SOD323]
VD_69  PartNumber: 1N4148  [DIODE: SOD323]
VD_70  PartNumber: 1N4148  [DIODE: SOD323]
VD_71  PartNumber: 1N4148  [DIODE: SOD323]
VD_72  PartNumber: 1N4148  [DIODE: SOD323]
VD_73  PartNumber: 1N4148  [DIODE: SOD323]
VD_74  PartNumber: 1N4148  [DIODE: SOD323]
VD_75  PartNumber: 1N4148  [DIODE: SOD323]
VD_76  PartNumber: 1N4148  [DIODE: SOD323]
VD_77  PartNumber: 1N4148  [DIODE: SOD323]
VD_78  PartNumber: 1N4148  [DIODE: SOD323]
VD_79  PartNumber: 1N4148  [DIODE: SOD323]
VD_80  PartNumber: 1N4148  [DIODE: SOD323]
VD_81  PartNumber: 1N4148  [DIODE: SOD323]
VD_82  PartNumber: 1N4148  [DIODE: SOD323]
VD_83  PartNumber: 1N4148  [DIODE: SOD323]
VD_84  PartNumber: 1N4148  [DIODE: SOD323]
VD_85  PartNumber: 1N4148  [DIODE: SOD323]
VD_86  PartNumber: 1N4148  [DIODE: SOD323]
VD_87  PartNumber: 1N4148  [DIODE: SOD323]
VD_88  PartNumber: 1N4148  [DIODE: SOD323]
VD_89  PartNumber: 1N4148  [DIODE: SOD323]
VD_90  PartNumber: 1N4148  [DIODE: SOD323]
VD_91  PartNumber: 1N4148  [DIODE: SOD323]
VD_92  PartNumber: 1N4148  [DIODE: SOD323]
VD_93  PartNumber: 1N4148  [DIODE: SOD323]
VD_94  PartNumber: 1N4148  [DIODE: SOD323]
VD_95  PartNumber: 1N4148  [DIODE: SOD323]
VD_96  PartNumber: 1N4148  [DIODE: SOD323]
VD_97  PartNumber: 1N4148  [DIODE: SOD323]
VD_98  PartNumber: 1N4148  [DIODE: SOD323]
VD_99  PartNumber: 1N4148  [DIODE: SOD323]
VD_100  PartNumber: 1N4148  [DIODE: SOD323]
VD_101  PartNumber: 1N4148  [DIODE: SOD323]
VD_102  PartNumber: 1N4148  [DIODE: SOD323]
VD_103  PartNumber: 1N4148  [DIODE: SOD323]
VD_104  PartNumber: 1N4148  [DIODE: SOD323]
VD_105  PartNumber: 1N4148  [DIODE: SOD323]
VD_106  PartNumber: 1N4148  [DIODE: SOD323]
VD_107  PartNumber: 1N4148  [DIODE: SOD323]
VD_108  PartNumber: 1N4148  [DIODE: SOD323]
VD_109  PartNumber: 1N4148  [DIODE: SOD323]
X1  CommentText: "USB"  [CON: USB Type-C P16]
X2  CommentText: "Разъем"  [CON: FFC 4pin 1mm]
Z1  Frequency: 8mHz  [OSC: 5032 2pins]

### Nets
+3.3: C3.2 C4.2 C5.2 C6.2 C8.1 D1.9(VDDA) D1.24(VDD) D1.36(VDD) D1.48(VDD) D2.2(VOUT) D2.4(VOUT) D3.6(VCCB) J1.1(IN) J2.1(IN) R7.2 R13.2 SW1.1 SW2.1 X2.4
+5: C7.1 C9.2 C10.2 C11.2 C12.2 C13.2 C14.2 C15.2 C16.2 C17.2 C18.2 C19.2 C20.2 C21.2 C22.2 C23.2 C24.2 C25.2 C26.2 C27.2 C28.2 C29.2 C30.2 C31.2 C32.2 C33.2 C34.2 C35.2 C36.2 C37.2 C38.2 C39.2 C40.2 C41.2 C42.2 C43.2 C44.2 C45.2 C46.2 C47.2 C48.2 C49.2 C50.2 C51.2 C52.2 C53.2 C54.2 C55.2 C56.2 C57.2 C58.2 C59.2 C60.2 C61.2 C62.2 C63.2 C64.2 C65.2 C66.2 C67.2 C68.2 C69.2 C70.2 C71.2 C72.2 C73.2 C74.2 C75.2 C76.2 C77.2 C78.2 C79.2 C80.2 C81.2 C82.2 C83.2 C84.2 C85.2 C86.2 C87.2 C88.2 C89.2 C90.2 C91.2 C92.2 C93.2 C94.2 C95.2 C96.2 C97.2 C98.2 C99.2 C100.2 C101.2 C102.2 C103.2 C104.2 C105.2 C106.2 C107.2 C108.2 C109.2 C110.2 C111.2 C112.2 C113.2 C114.2 C115.2 C116.2 C117.2 D2.3(VIN) D3.1(VCCA) D_0.4(VDD) D_1.4(VDD) D_2.4(VDD) D_3.4(VDD) D_4.4(VDD) D_5.4(VDD) D_6.4(VDD) D_7.4(VDD) D_8.4(VDD) D_9.4(VDD) D_'.4(VDD) D_+.4(VDD) D_-.4(VDD) D_;.4(VDD) D_<.4(VDD) D_>.4(VDD) D_?.4(VDD) D_[.4(VDD) D_\.4(VDD) D_].4(VDD) D_A.4(VDD) D_B.4(VDD) D_BACKSPACE.4(VDD) D_C.4(VDD) D_CAPSLOCK.4(VDD) D_D.4(VDD) D_Delete.4(VDD) D_Down.4(VDD) D_E.4(VDD) D_End.4(VDD) D_ENTER.4(VDD) D_ESC.4(VDD) D_F.4(VDD) D_F1.4(VDD) D_F2.4(VDD) D_F3.4(VDD) D_F4.4(VDD) D_F5.4(VDD) D_F6.4(VDD) D_F7.4(VDD) D_F8.4(VDD) D_F9.4(VDD) D_F10.4(VDD) D_F11.4(VDD) D_F12.4(VDD) D_G.4(VDD) D_H.4(VDD) D_Home.4(VDD) D_I.4(VDD) D_Insert.4(VDD) D_J.4(VDD) D_K.4(VDD) D_L.4(VDD) D_LALT.4(VDD) D_LCTRL.4(VDD) D_Left.4(VDD) D_LIST.4(VDD) D_LSHIFT.4(VDD) D_LSPACE.4(VDD) D_LWIN.4(VDD) D_M.4(VDD) D_MUTE.4(VDD) D_N.4(VDD) D_Num0.4(VDD) D_Num1.4(VDD) D_Num2.4(VDD) D_Num3.4(VDD) D_Num4.4(VDD) D_Num5.4(VDD) D_Num6.4(VDD) D_Num7.4(VDD) D_Num8.4(VDD) D_Num9.4(VDD) D_Num*.4(VDD) D_Num+.4(VDD) D_Num-.4(VDD) D_Num/.4(VDD) D_NumDot.4(VDD) D_NumEnter.4(VDD) D_NumLock.4(VDD) D_O.4(VDD) D_P.4(VDD) D_PageDown.4(VDD) D_PageUp.4(VDD) D_PauseBreak.4(VDD) D_PLAY.4(VDD) D_PrintScreen.4(VDD) D_Q.4(VDD) D_R.4(VDD) D_RALT.4(VDD) D_RCTRL.4(VDD) D_Right.4(VDD) D_RSHIFT.4(VDD) D_RSPACE.4(VDD) D_RWIN.4(VDD) D_S.4(VDD) D_ScrollLock.4(VDD) D_T.4(VDD) D_TAB.4(VDD) D_U.4(VDD) D_Up.4(VDD) D_V.4(VDD) D_VOL+.4(VDD) D_VOL-.4(VDD) D_W.4(VDD) D_X.4(VDD) D_Y.4(VDD) D_Z.4(VDD) D_~.4(VDD) F1.2 R14.2
+5_usb: F1.1 X1.VCC1 X1.VCC2
GND: C1.1 C2.1 C3.1 C4.1 C5.1 C6.1 C7.2 C8.2 C9.1 C10.1 C11.1 C12.1 C13.1 C14.1 C15.1 C16.1 C17.1 C18.1 C19.1 C20.1 C21.1 C22.1 C23.1 C24.1 C25.1 C26.1 C27.1 C28.1 C29.1 C30.1 C31.1 C32.1 C33.1 C34.1 C35.1 C36.1 C37.1 C38.1 C39.1 C40.1 C41.1 C42.1 C43.1 C44.1 C45.1 C46.1 C47.1 C48.1 C49.1 C50.1 C51.1 C52.1 C53.1 C54.1 C55.1 C56.1 C57.1 C58.1 C59.1 C60.1 C61.1 C62.1 C63.1 C64.1 C65.1 C66.1 C67.1 C68.1 C69.1 C70.1 C71.1 C72.1 C73.1 C74.1 C75.1 C76.1 C77.1 C78.1 C79.1 C80.1 C81.1 C82.1 C83.1 C84.1 C85.1 C86.1 C87.1 C88.1 C89.1 C90.1 C91.1 C92.1 C93.1 C94.1 C95.1 C96.1 C97.1 C98.1 C99.1 C100.1 C101.1 C102.1 C103.1 C104.1 C105.1 C106.1 C107.1 C108.1 C109.1 C110.1 C111.1 C112.1 C113.1 C114.1 C115.1 C116.1 C117.1 C118.1 D1.8(VSSA) D1.23(VSS) D1.35(VSS) D1.47(VSS) D2.1(GND) D3.2(GND) D3.5(DIR) D_0.2(GND) D_1.2(GND) D_2.2(GND) D_3.2(GND) D_4.2(GND) D_5.2(GND) D_6.2(GND) D_7.2(GND) D_8.2(GND) D_9.2(GND) D_'.2(GND) D_+.2(GND) D_-.2(GND) D_;.2(GND) D_<.2(GND) D_>.2(GND) D_?.2(GND) D_[.2(GND) D_\.2(GND) D_].2(GND) D_A.2(GND) D_B.2(GND) D_BACKSPACE.2(GND) D_C.2(GND) D_CAPSLOCK.2(GND) D_D.2(GND) D_Delete.2(GND) D_Down.2(GND) D_E.2(GND) D_End.2(GND) D_ENTER.2(GND) D_ESC.2(GND) D_F.2(GND) D_F1.2(GND) D_F2.2(GND) D_F3.2(GND) D_F4.2(GND) D_F5.2(GND) D_F6.2(GND) D_F7.2(GND) D_F8.2(GND) D_F9.2(GND) D_F10.2(GND) D_F11.2(GND) D_F12.2(GND) D_G.2(GND) D_H.2(GND) D_Home.2(GND) D_I.2(GND) D_Insert.2(GND) D_J.2(GND) D_K.2(GND) D_L.2(GND) D_LALT.2(GND) D_LCTRL.2(GND) D_Left.2(GND) D_LIST.2(GND) D_LSHIFT.2(GND) D_LSPACE.2(GND) D_LWIN.2(GND) D_M.2(GND) D_MUTE.2(GND) D_N.2(GND) D_Num0.2(GND) D_Num1.2(GND) D_Num2.2(GND) D_Num3.2(GND) D_Num4.2(GND) D_Num5.2(GND) D_Num6.2(GND) D_Num7.2(GND) D_Num8.2(GND) D_Num9.2(GND) D_Num*.2(GND) D_Num+.2(GND) D_Num-.2(GND) D_Num/.2(GND) D_NumDot.2(GND) D_NumEnter.2(GND) D_NumLock.2(GND) D_O.2(GND) D_P.2(GND) D_PageDown.2(GND) D_PageUp.2(GND) D_PauseBreak.2(GND) D_PLAY.2(GND) D_PrintScreen.2(GND) D_Q.2(GND) D_R.2(GND) D_RALT.2(GND) D_RCTRL.2(GND) D_Right.2(GND) D_RSHIFT.2(GND) D_RSPACE.2(GND) D_RWIN.2(GND) D_S.2(GND) D_ScrollLock.2(GND) D_T.2(GND) D_TAB.2(GND) D_U.2(GND) D_Up.2(GND) D_V.2(GND) D_VOL+.2(GND) D_VOL-.2(GND) D_W.2(GND) D_X.2(GND) D_Y.2(GND) D_Z.2(GND) D_~.2(GND) R1.1 R2.1 R10.2 R11.2 SW3.2 X1.GND1 X1.GND2 X2.1
BOOT0: D1.44(BOOT) R8.1
BOOT1: D1.20(PB2) R9.1
Col_1: D1.16(PA6) VD_1.2 VD_14.2 VD_28.2 VD_42.2 VD_55.2 VD_67.2
Col_2: D1.17(PA7) VD_2.2 VD_15.2 VD_29.2 VD_43.2 VD_56.2 VD_68.2
Col_3: D1.18(PB0) VD_3.2 VD_16.2 VD_30.2 VD_44.2 VD_57.2 VD_69.2
Col_4: D1.19(PB1) VD_4.2 VD_17.2 VD_31.2 VD_45.2 VD_58.2
Col_5: D1.21(PB10) VD_5.2 VD_18.2 VD_32.2 VD_46.2 VD_59.2 VD_70.2
Col_6: D1.22(PB11) VD_6.2 VD_19.2 VD_33.2 VD_47.2 VD_60.2
Col_7: D1.25(PB12) VD_7.2 VD_20.2 VD_34.2 VD_48.2 VD_61.2 VD_71.2
Col_8: D1.26(PB13) VD_8.2 VD_21.2 VD_35.2 VD_49.2 VD_62.2
Col_9: D1.27(PB14) VD_9.2 VD_22.2 VD_36.2 VD_50.2 VD_63.2 VD_72.2
Col_10: D1.28(PB15) VD_10.2 VD_23.2 VD_37.2 VD_51.2 VD_64.2 VD_73.2
Col_11: D1.29(PA8) VD_11.2 VD_24.2 VD_38.2 VD_52.2 VD_65.2 VD_74.2
Col_12: D1.30(PA9) VD_12.2 VD_25.2 VD_39.2 VD_53.2 VD_66.2 VD_75.2
Col_13: D1.31(PA10) VD_13.2 VD_26.2 VD_27.2 VD_40.2 VD_41.2 VD_54.2
Col_14: D1.45(PB8) VD_76.2 VD_83.2 VD_90.2 VD_105.2
Col_15: D1.46(PB9) VD_77.2 VD_84.2 VD_91.2 VD_100.2 VD_106.2
Col_16: D1.10(PA0) VD_78.2 VD_85.2 VD_92.2 VD_107.2
Col_17: D1.12(PA2) VD_79.2 VD_86.2 VD_93.2 VD_97.2 VD_101.2 VD_108.2
Col_18: D1.13(PA3) VD_80.2 VD_87.2 VD_94.2 VD_98.2 VD_102.2
Col_19: D1.14(PA4) VD_81.2 VD_88.2 VD_95.2 VD_99.2 VD_103.2 VD_109.2
Col_20: D1.15(PA5) VD_82.2 VD_89.2 VD_96.2 VD_104.2
DU_N: R4.1 X1.A7 X1.B7
DU_P: R3.1 X1.A6 X1.B6
JTCK: D1.37(SWCLK) X2.3
JTMS: D1.34(SWDIO) X2.2
LEDs_3.3: D1.11(PA1) R5.2
LEDs_5: D_Delete.3(DI) R6.1
RESET: C118.2 D1.7(NRST) R7.1 SW3.1
Row_1: D1.38(PA15) SW_ESC.2 SW_F1.2 SW_F2.2 SW_F3.2 SW_F4.2 SW_F5.2 SW_F6.2 SW_F7.2 SW_F8.2 SW_F9.2 SW_F10.2 SW_F11.2 SW_F12.2 SW_MUTE.2 SW_PauseBreak.2 SW_PLAY.2 SW_PrintScreen.2 SW_ScrollLock.2 SW_VOL+.2 SW_VOL_-.2
Row_2: D1.39(PB3) SW_0.2 SW_1.2 SW_2.2 SW_3.2 SW_4.2 SW_5.2 SW_6.2 SW_7.2 SW_8.2 SW_9.2 SW_+.2 SW_-.2 SW_Home.2 SW_Insert.2 SW_Num*.2 SW_Num-.2 SW_Num/.2 SW_NumLock.2 SW_PageUp.2 SW_~.2
Row_3: D1.40(PB4) SW_[.2 SW_].2 SW_Delete.2 SW_E.2 SW_End.2 SW_I.2 SW_Num7.2 SW_Num8.2 SW_Num9.2 SW_Num+.2 SW_O.2 SW_P.2 SW_PageDown.2 SW_Q.2 SW_R.2 SW_T.2 SW_TAB.2 SW_U.2 SW_W.2 SW_Y.2
Row_4: D1.41(PB5) SW_'.2 SW_;.2 SW_A.2 SW_CAPSLOCK.2 SW_D.2 SW_ENTER.2 SW_F.2 SW_G.2 SW_H.2 SW_J.2 SW_K.2 SW_L.2 SW_Num4.2 SW_Num5.2 SW_Num6.2 SW_S.2
Row_5: D1.42(PB6) SW_<.2 SW_>.2 SW_?.2 SW_B.2 SW_BACKSPACE.2 SW_C.2 SW_LSHIFT.2 SW_M.2 SW_N.2 SW_Num1.2 SW_Num2.2 SW_Num3.2 SW_NumEnter.2 SW_RSHIFT.2 SW_Up.2 SW_V.2 SW_X.2 SW_Z.2
Row_6: D1.43(PB7) SW_\.2 SW_Down.2 SW_LALT.2 SW_LCTRL.2 SW_Left.2 SW_LIST.2 SW_LSPACE.2 SW_LWIN.2 SW_Num0.2 SW_NumDot.2 SW_RALT.2 SW_RCTRL.2 SW_Right.2 SW_RSPACE.2 SW_RWIN.2
NetC1_2: C1.2 D1.6(OSC_OUT) Z1.1
NetC2_2: C2.2 D1.5(OSC_IN) Z1.2
NetD1_32: D1.32(PA11) R4.2
NetD1_33: D1.33(PA12) R3.2 R12.1
NetD3_3: D3.3(A) R6.2
NetD3_4: D3.4(B) R5.1
NetD_0_1: D_0.1(DO) D_9.3(DI)
NetD_0_3: D_0.3(DI) D_-.1(DO)
NetD_1_1: D_1.1(DO) D_~.3(DI)
NetD_1_3: D_1.3(DI) D_2.1(DO)
NetD_2_3: D_2.3(DI) D_3.1(DO)
NetD_3_3: D_3.3(DI) D_4.1(DO)
NetD_4_3: D_4.3(DI) D_5.1(DO)
NetD_5_3: D_5.3(DI) D_6.1(DO)
NetD_6_3: D_6.3(DI) D_7.1(DO)
NetD_7_3: D_7.3(DI) D_8.1(DO)
NetD_8_3: D_8.3(DI) D_9.1(DO)
NetD_'_1: D_'.1(DO) D_;.3(DI)
NetD_'_3: D_'.3(DI) D_ENTER.1(DO)
NetD_+_1: D_+.1(DO) D_-.3(DI)
NetD_+_3: D_+.3(DI) D_BACKSPACE.1(DO)
NetD_;_1: D_;.1(DO) D_L.3(DI)
NetD_<_1: D_<.1(DO) D_>.3(DI)
NetD_<_3: D_<.3(DI) D_M.1(DO)
NetD_>_1: D_>.1(DO) D_?.3(DI)
NetD_?_1: D_?.1(DO) D_RSHIFT.3(DI)
NetD_[_1: D_[.1(DO) D_].3(DI)
NetD_[_3: D_[.3(DI) D_P.1(DO)
NetD~{_}_1: D_\.1(DO) D_BACKSPACE.3(DI)
NetD~{_}_3: D_\.3(DI) D_].1(DO)
NetD_A_1: D_A.1(DO) D_CAPSLOCK.3(DI)
NetD_A_3: D_A.3(DI) D_S.1(DO)
NetD_B_1: D_B.1(DO) D_N.3(DI)
NetD_B_3: D_B.3(DI) D_V.1(DO)
NetD_C_1: D_C.1(DO) D_V.3(DI)
NetD_C_3: D_C.3(DI) D_X.1(DO)
NetD_CAPSLOCK_1: D_CAPSLOCK.1(DO) D_TAB.3(DI)
NetD_D_1: D_D.1(DO) D_S.3(DI)
NetD_D_3: D_D.3(DI) D_F.1(DO)
NetD_Delete_1: D_Delete.1(DO) D_End.3(DI)
NetD_Down_1: D_Down.1(DO) D_Up.3(DI)
NetD_Down_3: D_Down.3(DI) D_Right.1(DO)
NetD_E_1: D_E.1(DO) D_R.3(DI)
NetD_E_3: D_E.3(DI) D_W.1(DO)
NetD_End_1: D_End.1(DO) D_PageDown.3(DI)
NetD_ENTER_3: D_ENTER.3(DI) D_RSHIFT.1(DO)
NetD_ESC_1: D_ESC.1(DO) D_F1.3(DI)
NetD_ESC_3: D_ESC.3(DI) D_~.1(DO)
NetD_F1_1: D_F1.1(DO) D_F2.3(DI)
NetD_F2_1: D_F2.1(DO) D_F3.3(DI)
NetD_F3_1: D_F3.1(DO) D_F4.3(DI)
NetD_F4_1: D_F4.1(DO) D_F5.3(DI)
NetD_F5_1: D_F5.1(DO) D_F6.3(DI)
NetD_F6_1: D_F6.1(DO) D_F7.3(DI)
NetD_F7_1: D_F7.1(DO) D_F8.3(DI)
NetD_F8_1: D_F8.1(DO) D_F9.3(DI)
NetD_F9_1: D_F9.1(DO) D_F10.3(DI)
NetD_F10_1: D_F10.1(DO) D_F11.3(DI)
NetD_F11_1: D_F11.1(DO) D_F12.3(DI)
NetD_F_3: D_F.3(DI) D_G.1(DO)
NetD_G_3: D_G.3(DI) D_H.1(DO)
NetD_H_3: D_H.3(DI) D_J.1(DO)
NetD_Home_1: D_Home.1(DO) D_Insert.3(DI)
NetD_Home_3: D_Home.3(DI) D_PageUp.1(DO)
NetD_I_1: D_I.1(DO) D_O.3(DI)
NetD_I_3: D_I.3(DI) D_U.1(DO)
NetD_Insert_1: D_Insert.1(DO) D_PrintScreen.3(DI)
NetD_J_3: D_J.3(DI) D_K.1(DO)
NetD_K_3: D_K.3(DI) D_L.1(DO)
NetD_LALT_1: D_LALT.1(DO) D_LWIN.3(DI)
NetD_LALT_3: D_LALT.3(DI) D_LSPACE.1(DO)
NetD_LCTRL_1: D_LCTRL.1(DO) D_LSHIFT.3(DI)
NetD_LCTRL_3: D_LCTRL.3(DI) D_LWIN.1(DO)
NetD_Left_1: D_Left.1(DO) D_RCTRL.3(DI)
NetD_Left_3: D_Left.3(DI) D_Up.1(DO)
NetD_LIST_1: D_LIST.1(DO) D_RWIN.3(DI)
NetD_LIST_3: D_LIST.3(DI) D_RCTRL.1(DO)
NetD_LSHIFT_1: D_LSHIFT.1(DO) D_Z.3(DI)
NetD_LSPACE_3: D_LSPACE.3(DI) D_RSPACE.1(DO)
NetD_M_3: D_M.3(DI) D_N.1(DO)
NetD_MUTE_1: D_MUTE.1(DO) D_Num-.3(DI)
NetD_MUTE_3: D_MUTE.3(DI) D_VOL+.1(DO)
NetD_Num0_1: D_Num0.1(DO) D_Right.3(DI)
NetD_Num0_3: D_Num0.3(DI) D_NumDot.1(DO)
NetD_Num1_1: D_Num1.1(DO) D_Num2.3(DI)
NetD_Num1_3: D_Num1.3(DI) D_Num4.1(DO)
NetD_Num2_1: D_Num2.1(DO) D_Num3.3(DI)
NetD_Num3_1: D_Num3.1(DO) D_NumEnter.3(DI)
NetD_Num4_3: D_Num4.3(DI) D_Num5.1(DO)
NetD_Num5_3: D_Num5.3(DI) D_Num6.1(DO)
NetD_Num6_3: D_Num6.3(DI) D_Num+.1(DO)
NetD_Num7_1: D_Num7.1(DO) D_Num8.3(DI)
NetD_Num7_3: D_Num7.3(DI) D_NumLock.1(DO)
NetD_Num8_1: D_Num8.1(DO) D_Num9.3(DI)
NetD_Num9_1: D_Num9.1(DO) D_Num+.3(DI)
NetD_Num*_1: D_Num*.1(DO) D_Num/.3(DI)
NetD_Num*_3: D_Num*.3(DI) D_Num-.1(DO)
NetD_Num/_1: D_Num/.1(DO) D_NumLock.3(DI)
NetD_NumDot_3: D_NumDot.3(DI) D_NumEnter.1(DO)
NetD_O_1: D_O.1(DO) D_P.3(DI)
NetD_PageDown_1: D_PageDown.1(DO) D_PageUp.3(DI)
NetD_PauseBreak_1: D_PauseBreak.1(DO) D_PLAY.3(DI)
NetD_PauseBreak_3: D_PauseBreak.3(DI) D_ScrollLock.1(DO)
NetD_PLAY_1: D_PLAY.1(DO) D_VOL-.3(DI)
NetD_PrintScreen_1: D_PrintScreen.1(DO) D_ScrollLock.3(DI)
NetD_Q_1: D_Q.1(DO) D_W.3(DI)
NetD_Q_3: D_Q.3(DI) D_TAB.1(DO)
NetD_R_1: D_R.1(DO) D_T.3(DI)
NetD_RALT_1: D_RALT.1(DO) D_RSPACE.3(DI)
NetD_RALT_3: D_RALT.3(DI) D_RWIN.1(DO)
NetD_T_1: D_T.1(DO) D_Y.3(DI)
NetD_U_3: D_U.3(DI) D_Y.1(DO)
NetD_VOL+_3: D_VOL+.3(DI) D_VOL-.1(DO)
NetD_X_3: D_X.3(DI) D_Z.1(DO)
NetJ1_2: J1.2(IN) R8.2 R10.1 SW1.2
NetJ2_2: J2.2(IN) R9.2 R11.1 SW2.2
NetR1_2: R1.2 X1.A5
NetR2_2: R2.2 X1.B5
NetR12_2: R12.2 R13.1 R14.1
NetSW_0_1: SW_0.1 VD_24.1
NetSW_1_1: SW_1.1 VD_15.1
NetSW_2_1: SW_2.1 VD_16.1
NetSW_3_1: SW_3.1 VD_17.1
NetSW_4_1: SW_4.1 VD_18.1
NetSW_5_1: SW_5.1 VD_19.1
NetSW_6_1: SW_6.1 VD_20.1
NetSW_7_1: SW_7.1 VD_21.1
NetSW_8_1: SW_8.1 VD_22.1
NetSW_9_1: SW_9.1 VD_23.1
NetSW_'_1: SW_'.1 VD_53.1
NetSW_+_1: SW_+.1 VD_26.1
NetSW_-_1: SW_-.1 VD_25.1
NetSW_;_1: SW_;.1 VD_52.1
NetSW_<_1: SW_<.1 VD_63.1
NetSW_>_1: SW_>.1 VD_64.1
NetSW_?_1: SW_?.1 VD_65.1
NetSW_[_1: SW_[.1 VD_39.1
NetSW~{_}_1: SW_\.1 VD_41.1
NetSW_]_1: SW_].1 VD_40.1
NetSW_A_1: SW_A.1 VD_43.1
NetSW_B_1: SW_B.1 VD_60.1
NetSW_BACKSPACE_1: SW_BACKSPACE.1 VD_27.1
NetSW_C_1: SW_C.1 VD_58.1
NetSW_CAPSLOCK_1: SW_CAPSLOCK.1 VD_42.1
NetSW_D_1: SW_D.1 VD_45.1
NetSW_Delete_1: SW_Delete.1 VD_90.1
NetSW_Down_1: SW_Down.1 VD_106.1
NetSW_E_1: SW_E.1 VD_31.1
NetSW_End_1: SW_End.1 VD_91.1
NetSW_ENTER_1: SW_ENTER.1 VD_54.1
NetSW_ESC_1: SW_ESC.1 VD_1.1
NetSW_F1_1: SW_F1.1 VD_2.1
NetSW_F2_1: SW_F2.1 VD_3.1
NetSW_F3_1: SW_F3.1 VD_4.1
NetSW_F4_1: SW_F4.1 VD_5.1
NetSW_F5_1: SW_F5.1 VD_6.1
NetSW_F6_1: SW_F6.1 VD_7.1
NetSW_F7_1: SW_F7.1 VD_8.1
NetSW_F8_1: SW_F8.1 VD_9.1
NetSW_F9_1: SW_F9.1 VD_10.1
NetSW_F10_1: SW_F10.1 VD_11.1
NetSW_F11_1: SW_F11.1 VD_12.1
NetSW_F12_1: SW_F12.1 VD_13.1
NetSW_F_1: SW_F.1 VD_46.1
NetSW_G_1: SW_G.1 VD_47.1
NetSW_H_1: SW_H.1 VD_48.1
NetSW_Home_1: SW_Home.1 VD_84.1
NetSW_I_1: SW_I.1 VD_36.1
NetSW_Insert_1: SW_Insert.1 VD_83.1
NetSW_J_1: SW_J.1 VD_49.1
NetSW_K_1: SW_K.1 VD_50.1
NetSW_L_1: SW_L.1 VD_51.1
NetSW_LALT_1: SW_LALT.1 VD_69.1
NetSW_LCTRL_1: SW_LCTRL.1 VD_67.1
NetSW_Left_1: SW_Left.1 VD_105.1
NetSW_LIST_1: SW_LIST.1 VD_74.1
NetSW_LSHIFT_1: SW_LSHIFT.1 VD_55.1
NetSW_LSPACE_1: SW_LSPACE.1 VD_70.1
NetSW_LWIN_1: SW_LWIN.1 VD_68.1
NetSW_M_1: SW_M.1 VD_62.1
NetSW_MUTE_1: SW_MUTE.1 VD_82.1
NetSW_N_1: SW_N.1 VD_61.1
NetSW_Num0_1: SW_Num0.1 VD_108.1
NetSW_Num1_1: SW_Num1.1 VD_101.1
NetSW_Num2_1: SW_Num2.1 VD_102.1
NetSW_Num3_1: SW_Num3.1 VD_103.1
NetSW_Num4_1: SW_Num4.1 VD_97.1
NetSW_Num5_1: SW_Num5.1 VD_98.1
NetSW_Num6_1: SW_Num6.1 VD_99.1
NetSW_Num7_1: SW_Num7.1 VD_93.1
NetSW_Num8_1: SW_Num8.1 VD_94.1
NetSW_Num9_1: SW_Num9.1 VD_95.1
NetSW_Num*_1: SW_Num*.1 VD_88.1
NetSW_Num+_1: SW_Num+.1 VD_96.1
NetSW_Num-_1: SW_Num-.1 VD_89.1
NetSW_Num/_1: SW_Num/.1 VD_87.1
NetSW_NumDot_1: SW_NumDot.1 VD_109.1
NetSW_NumEnter_1: SW_NumEnter.1 VD_104.1
NetSW_NumLock_1: SW_NumLock.1 VD_86.1
NetSW_O_1: SW_O.1 VD_37.1
NetSW_P_1: SW_P.1 VD_38.1
NetSW_PageDown_1: SW_PageDown.1 VD_92.1
NetSW_PageUp_1: SW_PageUp.1 VD_85.1
NetSW_PauseBreak_1: SW_PauseBreak.1 VD_78.1
NetSW_PLAY_1: SW_PLAY.1 VD_79.1
NetSW_PrintScreen_1: SW_PrintScreen.1 VD_76.1
NetSW_Q_1: SW_Q.1 VD_29.1
NetSW_R_1: SW_R.1 VD_32.1
NetSW_RALT_1: SW_RALT.1 VD_72.1
NetSW_RCTRL_1: SW_RCTRL.1 VD_75.1
NetSW_Right_1: SW_Right.1 VD_107.1
NetSW_RSHIFT_1: SW_RSHIFT.1 VD_66.1
NetSW_RSPACE_1: SW_RSPACE.1 VD_71.1
NetSW_RWIN_1: SW_RWIN.1 VD_73.1
NetSW_S_1: SW_S.1 VD_44.1
NetSW_ScrollLock_1: SW_ScrollLock.1 VD_77.1
NetSW_T_1: SW_T.1 VD_33.1
NetSW_TAB_1: SW_TAB.1 VD_28.1
NetSW_U_1: SW_U.1 VD_35.1
NetSW_Up_1: SW_Up.1 VD_100.1
NetSW_V_1: SW_V.1 VD_59.1
NetSW_VOL+_1: SW_VOL+.1 VD_81.1
NetSW_VOL_-_1: SW_VOL_-.1 VD_80.1
NetSW_W_1: SW_W.1 VD_30.1
NetSW_X_1: SW_X.1 VD_57.1
NetSW_Y_1: SW_Y.1 VD_34.1
NetSW_Z_1: SW_Z.1 VD_56.1
NetSW_~_1: SW_~.1 VD_14.1

Not connected (* = marked no-connect by the designer): D1 1(VBAT) 2(PC13) 3(PC14) 4(PC15); D_F12 1(DO); X1 A8 B8

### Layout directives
differential pair: DU_N, DU_P

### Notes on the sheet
- (near R6) DIR = L, DIR = B->A
- DIR = H, DIR = A->B

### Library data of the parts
C1-C6 C9-C118 = Ceramic_0603: Manufacturer: Yageo; PartNumber: CC0603KRX7R7BB104; TypeCapacitor: Ceramic capacitor; Tolerance: ±10%; TypeDielectric: X7R
C7 C8 = Tantal_A: Manufacturer: AVX; PartNumber: F930J107KAAAJ6; ValueManufacturerPartNumber: Tantalum capacitor, 10μF, 16V, ±10%, 2Ohm, case A (3216), -55...+125°C; Impedance: 2Ohm; Tolerance: ±10%; TypeDielectric: X7R; TypeCapacitor: Tantalum capacitor
D1 = STM32F103C8T6: Cortex-M3; Manufacturer: STMicroelectronics; ValueManufacturerPartNumber: IC microcontroller, 32-Bit, Cortex-M3, 72MHz, 64KB, 20KB, 2...3.6V, -40...+85°C, 48-LQFP; Supply: 2...3.6V; Speed: 72MHz; CoreSize: 32-Bit; MemoryROM: 64KB; MemoryRAM: 20KB
D2 = LDL1117S33R: Linear voltage regulator; Manufacturer: STMicroelectronics; ValueManufacturerPartNumber: Linear voltage regulator, input 3.9...18V, 0.6V, output 3.3V, 1.2A, -40...+85°C, SOT223; VoltageInput: input 3.9...18V; MaxDropout: 0.6V; CurrentOutput: 1.2A; VoltageOutput: output 3.3V
D3 = SN74LVC1T45: Digital isolator; Manufacturer: Texas Instruments
D_0-D_9 D_' D_+ D_- D_; D_< D_> D_? D_[ D_\ D_] D_A D_B D_BACKSPACE D_C D_CAPSLOCK D_D D_Delete D_Down D_E D_End D_ENTER D_ESC D_F D_F1-D_F12 D_G D_H D_Home D_I D_Insert D_J D_K D_L D_LALT D_LCTRL D_Left D_LIST D_LSHIFT D_LSPACE D_LWIN D_M D_MUTE D_N D_Num0-D_Num9 D_Num* D_Num+ D_Num- D_Num/ D_NumDot D_NumEnter D_NumLock D_O D_P D_PageDown D_PageUp D_PauseBreak D_PLAY D_PrintScreen D_Q D_R D_RALT D_RCTRL D_Right D_RSHIFT D_RSPACE D_RWIN D_S D_ScrollLock D_T D_TAB D_U D_Up D_V D_VOL+ D_VOL- D_W D_X D_Y D_Z D_~ = YF923 2020: Manufacturer: STMicroelectronics; TypeDiode: USB protection; Current: 5A peak; VoltageDrop: 17V; RecoveryTime: Power line
F1 = Resistor_1206: Manufacturer: Yageo; PartNumber: RC1206JR-07100RL
J1 J2 = Jumper_single
R1-R14 = Resistor_0603: Manufacturer: Yageo; PartNumber: RC0603JR-07100RL
SW1-SW3 = Button_3x4x2_SMT: SMT 3*4*2 2PIN; Manufacturer: xin cheng electronic
SW_0-SW_9 SW_' SW_+ SW_- SW_; SW_< SW_> SW_? SW_[ SW_\ SW_] SW_A SW_B SW_BACKSPACE SW_C SW_CAPSLOCK SW_D SW_Delete SW_Down SW_E SW_End SW_ENTER SW_ESC SW_F SW_F1-SW_F12 SW_G SW_H SW_Home SW_I SW_Insert SW_J SW_K SW_L SW_LALT SW_LCTRL SW_Left SW_LIST SW_LSHIFT SW_LSPACE SW_LWIN SW_M SW_MUTE SW_N SW_Num0-SW_Num9 SW_Num* SW_Num+ SW_Num- SW_Num/ SW_NumDot SW_NumEnter SW_NumLock SW_O SW_P SW_PageDown SW_PageUp SW_PauseBreak SW_PLAY SW_PrintScreen SW_Q SW_R SW_RALT SW_RCTRL SW_Right SW_RSHIFT SW_RSPACE SW_RWIN SW_S SW_ScrollLock SW_T SW_TAB SW_U SW_Up SW_V SW_VOL+ SW_VOL_- SW_W SW_X SW_Y SW_Z SW_~ = Button_kailh: Manufacturer: xin cheng electronic; PartNumber: 3*4*2 2PIN
VD_1-VD_109 = Schottky_single: Manufacturer: Diodes Incorporated; ValueManufacturerPartNumber: Schottky diode, 80V, 500mA, 1V, 15pF, SOD-123, -55...+150°C; TypeDiode: Schottky diode; Voltage: 80V; Current: 500mA; VoltageDrop: 1V; RecoveryTime: 15pF
X1 = Connector_USB_typeC 16P: Manufacturer: Molex; ValueManufacturerPartNumber: USB mini B; PartNumber: 0675031020
X2 = Connector_FPC_4_1mm: Manufacturer: JST; ValueManufacturerPartNumber: Connector, 4pin, 1.25mm, 50VDC, 1A; PartNumber: SM04B-GHS; VoltageMax: 50VDC; Pitch: 1.25mm; CurrentMax: 1A; Multichannel: 4pin
Z1 = Crystal_3215: Manufacturer: Epson; PartNumber: FC-135 32.7680KA-A5; ValueManufacturerPartNumber: Crystal, 8mHz, 12.5pF, ±20ppm, case 3215, -40...+85°C; LoadCapacitance: 12.5pF; Tolerance: ±20ppm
